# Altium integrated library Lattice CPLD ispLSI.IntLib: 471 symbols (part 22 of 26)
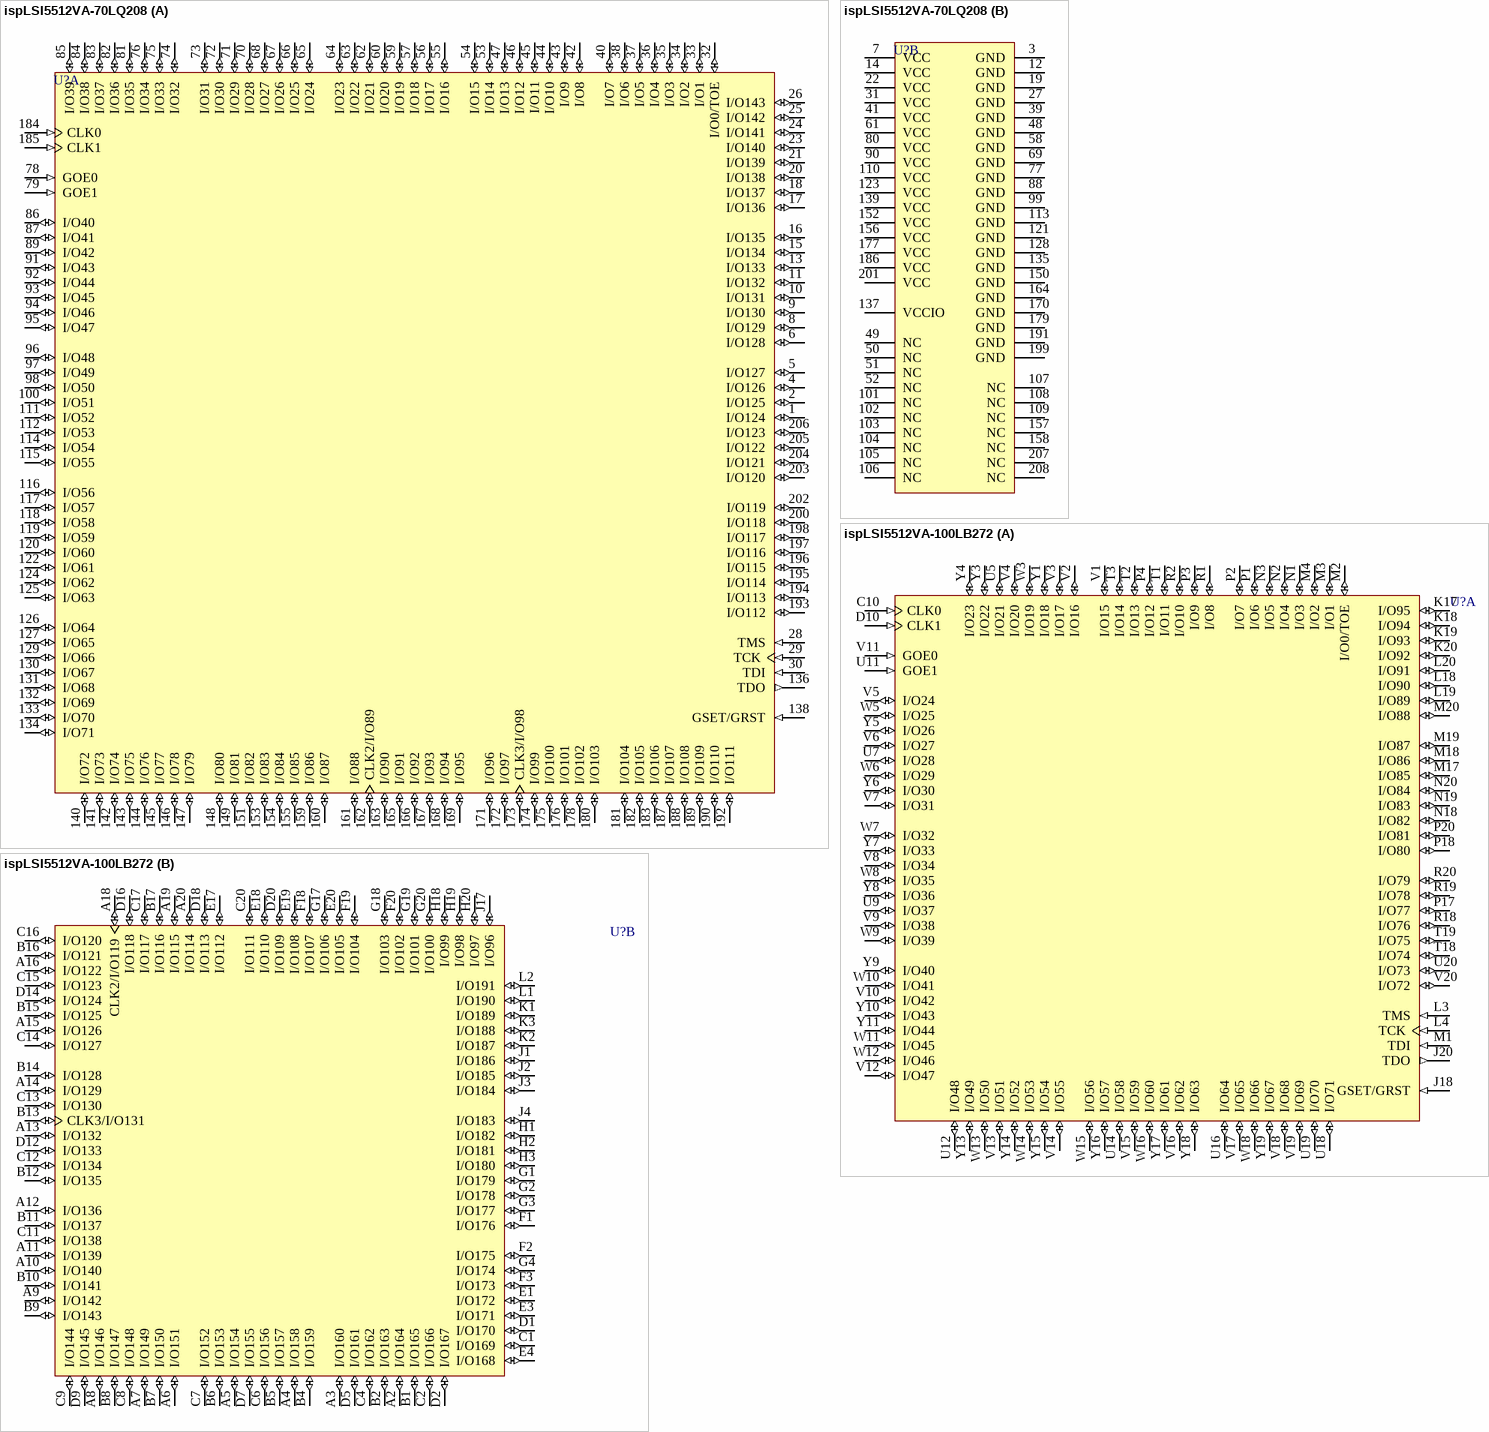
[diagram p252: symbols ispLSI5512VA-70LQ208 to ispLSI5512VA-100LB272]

## ispLSI5512VA-70LQ208
designator U?
In-System Programmable 3.3V SuperWIDE High Density PLD
footprint PQFP208_N (Shrink QFP, 208-Leads, Body 28x28mm, Pitch 0.5mm, IPC Medium Density)
footprint PQFP208_L (Shrink QFP, 208-Leads, Body 28x28mm, Pitch 0.5mm, IPC High Density)
footprint PQFP208_M (Shrink QFP, 208-Leads, Body 28x28mm, Pitch 0.5mm, IPC Low Density)
3D model 5512VA-PQFP208 (208-Pin Plastic Quad Flat Pack (PQFP208))
part A pins: 1 I/O124 (io), 2 I/O125 (io), 4 I/O126 (io), 5 I/O127 (io), 6 I/O128 (io), 8 I/O129 (io), 9 I/O130 (io), 10 I/O131 (io), 11 I/O132 (io), 13 I/O133 (io), 15 I/O134 (io), 16 I/O135 (io), 17 I/O136 (io), 18 I/O137 (io), 20 I/O138 (io), 21 I/O139 (io), 23 I/O140 (io), 24 I/O141 (io), 25 I/O142 (io), 26 I/O143 (io), 28 TMS (in), 29 TCK (in), 30 TDI (in), 32 I/O0/TOE (io), 33 I/O1 (io), 34 I/O2 (io), 35 I/O3 (io), 36 I/O4 (io), 37 I/O5 (io), 38 I/O6 (io), 40 I/O7 (io), 42 I/O8 (io), 43 I/O9 (io), 44 I/O10 (io), 45 I/O11 (io), 46 I/O12 (io), 47 I/O13 (io), 53 I/O14 (io), 54 I/O15 (io), 55 I/O16 (io), 56 I/O17 (io), 57 I/O18 (io), 59 I/O19 (io), 60 I/O20 (io), 62 I/O21 (io), 63 I/O22 (io), 64 I/O23 (io), 65 I/O24 (io), 66 I/O25 (io), 67 I/O26 (io), 68 I/O27 (io), 70 I/O28 (io), 71 I/O29 (io), 72 I/O30 (io), 73 I/O31 (io), 74 I/O32 (io), 75 I/O33 (io), 76 I/O34 (io), 78 GOE0 (in), 79 GOE1 (in), 81 I/O35 (io), 82 I/O36 (io), 83 I/O37 (io), 84 I/O38 (io), 85 I/O39 (io), 86 I/O40 (io), 87 I/O41 (io), 89 I/O42 (io), 91 I/O43 (io), 92 I/O44 (io), 93 I/O45 (io), 94 I/O46 (io), 95 I/O47 (io), 96 I/O48 (io), 97 I/O49 (io), 98 I/O50 (io), 100 I/O51 (io), 111 I/O52 (io), 112 I/O53 (io), 114 I/O54 (io), 115 I/O55 (io), 116 I/O56 (io), 117 I/O57 (io), 118 I/O58 (io), 119 I/O59 (io), 120 I/O60 (io), 122 I/O61 (io), 124 I/O62 (io), 125 I/O63 (io), 126 I/O64 (io), 127 I/O65 (io), 129 I/O66 (io), 130 I/O67 (io), 131 I/O68 (io), 132 I/O69 (io), 133 I/O70 (io), 134 I/O71 (io), 136 TDO (out), 138 GSET/GRST (in), 140 I/O72 (io), 141 I/O73 (io), 142 I/O74 (io), 143 I/O75 (io), 144 I/O76 (io), 145 I/O77 (io), 146 I/O78 (io), 147 I/O79 (io), 148 I/O80 (io), 149 I/O81 (io), 151 I/O82 (io), 153 I/O83 (io), 154 I/O84 (io), 155 I/O85 (io), 159 I/O86 (io), 160 I/O87 (io), 161 I/O88 (io), 162 CLK2/I/O89 (io), 163 I/O90 (io), 165 I/O91 (io), 166 I/O92 (io), 167 I/O93 (io), 168 I/O94 (io), 169 I/O95 (io), 171 I/O96 (io), 172 I/O97 (io), 173 CLK3/I/O98 (io), 174 I/O99 (io), 175 I/O100 (io), 176 I/O101 (io), 178 I/O102 (io), 180 I/O103 (io), 181 I/O104 (io), 182 I/O105 (io), 183 I/O106 (io), 184 CLK0 (in), 185 CLK1 (in), 187 I/O107 (io), 188 I/O108 (io), 189 I/O109 (io), 190 I/O110 (io), 192 I/O111 (io), 193 I/O112 (io), 194 I/O113 (io), 195 I/O114 (io), 196 I/O115 (io), 197 I/O116 (io), 198 I/O117 (io), 200 I/O118 (io), 202 I/O119 (io), 203 I/O120 (io), 204 I/O121 (io), 205 I/O122 (io), 206 I/O123 (io)
part B pins: 3 GND (power), 7 VCC (power), 12 GND (power), 14 VCC (power), 19 GND (power), 22 VCC (power), 27 GND (power), 31 VCC (power), 39 GND (power), 41 VCC (power), 48 GND (power), 49 NC, 50 NC, 51 NC, 52 NC, 58 GND (power), 61 VCC (power), 69 GND (power), 77 GND (power), 80 VCC (power), 88 GND (power), 90 VCC (power), 99 GND (power), 101 NC, 102 NC, 103 NC, 104 NC, 105 NC, 106 NC, 107 NC, 108 NC, 109 NC, 110 VCC (power), 113 GND (power), 121 GND (power), 123 VCC (power), 128 GND (power), 135 GND (power), 137 VCCIO (power), 139 VCC (power), 150 GND (power), 152 VCC (power), 156 VCC (power), 157 NC, 158 NC, 164 GND (power), 170 GND (power), 177 VCC (power), 179 GND (power), 186 VCC (power), 191 GND (power), 199 GND (power), 201 VCC (power), 207 NC, 208 NC

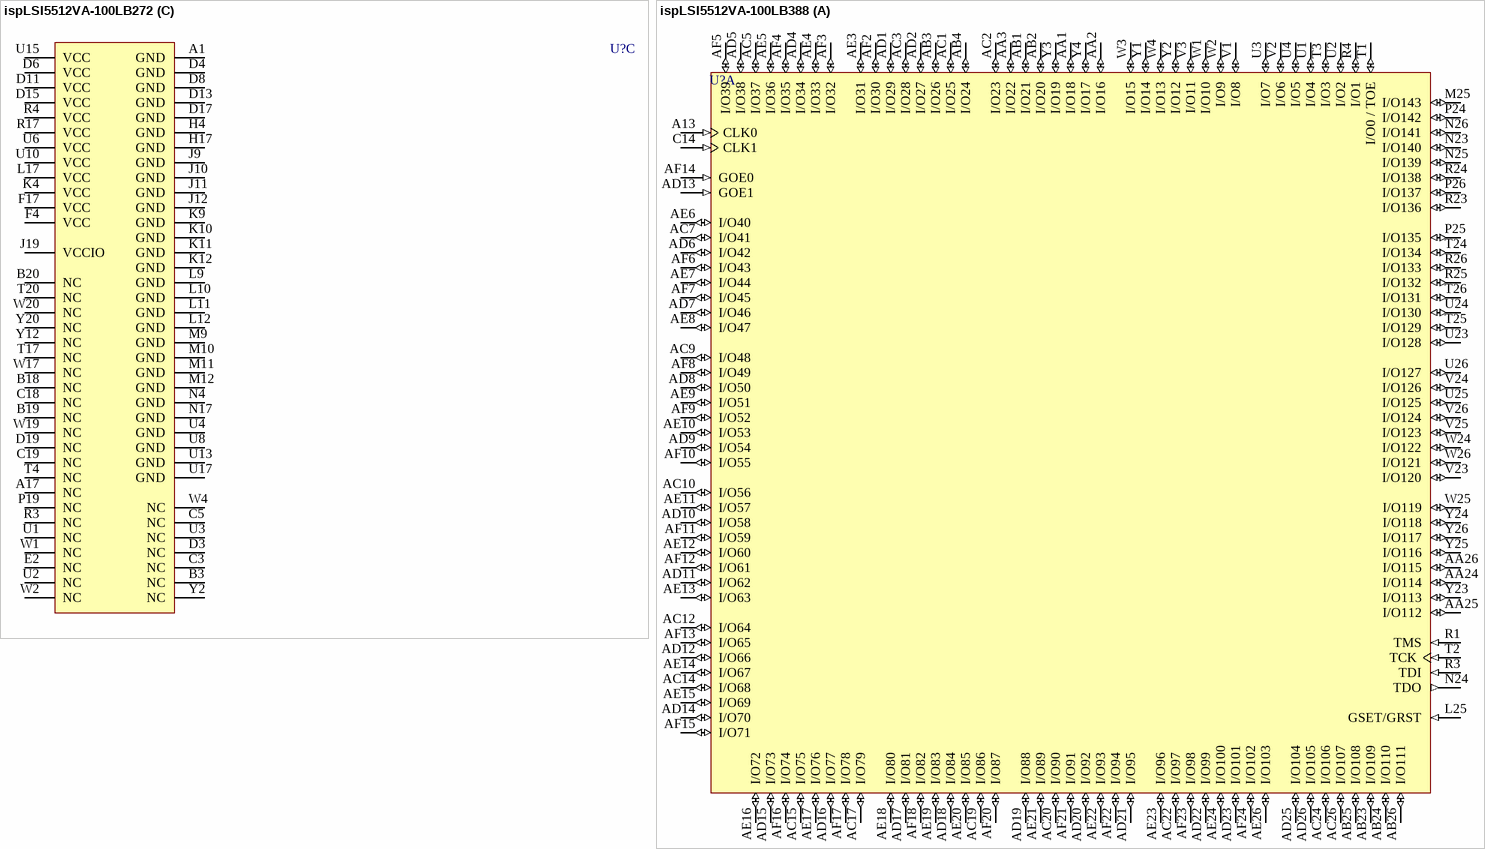
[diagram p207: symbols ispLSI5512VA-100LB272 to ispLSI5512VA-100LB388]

## ispLSI5512VA-100LB272
designator U?
In-System Programmable 3.3V SuperWIDE High Density PLD
footprint BGA272 (BGA, 272-Leads, Body 27x27mm, Pitch 1.27mm)
3D model 5512VA-BGA272 (272-Ball Ball Grid Array (BGA272))
part A pins: C10 CLK0 (in), D10 CLK1 (in), J18 GSET/GRST (in), J20 TDO (out), K17 I/O95 (io), K18 I/O94 (io), K19 I/O93 (io), K20 I/O92 (io), L3 TMS (in), L4 TCK (in), L18 I/O90 (io), L19 I/O89 (io), L20 I/O91 (io), M1 TDI (in), M2 I/O0/TOE (io), M3 I/O1 (io), M4 I/O2 (io), M17 I/O85 (io), M18 I/O86 (io), M19 I/O87 (io), M20 I/O88 (io), N1 I/O3 (io), N2 I/O4 (io), N3 I/O5 (io), N18 I/O82 (io), N19 I/O83 (io), N20 I/O84 (io), P1 I/O6 (io), P2 I/O7 (io), P3 I/O9 (io), P4 I/O12 (io), P17 I/O77 (io), P18 I/O80 (io), P20 I/O81 (io), R1 I/O8 (io), R2 I/O10 (io), R18 I/O76 (io), R19 I/O78 (io), R20 I/O79 (io), T1 I/O11 (io), T2 I/O13 (io), T3 I/O14 (io), T18 I/O74 (io), T19 I/O75 (io), U5 I/O21 (io), U7 I/O28 (io), U9 I/O37 (io), U11 GOE1 (in), U12 I/O48 (io), U14 I/O58 (io), U16 I/O64 (io), U18 I/O71 (io), U19 I/O70 (io), U20 I/O73 (io), V1 I/O15 (io), V2 I/O16 (io), V3 I/O17 (io), V4 I/O20 (io), V5 I/O24 (io), V6 I/O27 (io), V7 I/O31 (io), V8 I/O34 (io), V9 I/O38 (io), V10 I/O42 (io), V11 GOE0 (in), V12 I/O47 (io), V13 I/O51 (io), V14 I/O55 (io), V15 I/O59 (io), V16 I/O62 (io), V17 I/O65 (io), V18 I/O68 (io), V19 I/O69 (io), V20 I/O72 (io), W3 I/O19 (io), W5 I/O25 (io), W6 I/O29 (io), W7 I/O32 (io), W8 I/O35 (io), W9 I/O39 (io), W10 I/O41 (io), W11 I/O45 (io), W12 I/O46 (io), W13 I/O50 (io), W14 I/O53 (io), W15 I/O56 (io), W16 I/O60 (io), W18 I/O66 (io), Y1 I/O18 (io), Y3 I/O22 (io), Y4 I/O23 (io), Y5 I/O26 (io), Y6 I/O30 (io), Y7 I/O33 (io), Y8 I/O36 (io), Y9 I/O40 (io), Y10 I/O43 (io), Y11 I/O44 (io), Y13 I/O49 (io), Y14 I/O52 (io), Y15 I/O54 (io), Y16 I/O57 (io), Y17 I/O61 (io), Y18 I/O63 (io), Y19 I/O67 (io)
part B pins: A2 I/O164 (io), A3 I/O160 (io), A4 I/O158 (io), A5 I/O154 (io), A6 I/O151 (io), A7 I/O149 (io), A8 I/O146 (io), A9 I/O142 (io), A10 I/O140 (io), A11 I/O139 (io), A12 I/O136 (io), A13 I/O132 (io), A14 I/O129 (io), A15 I/O126 (io), A16 I/O122 (io), A18 CLK2/I/O119 (io), A19 I/O115 (io), A20 I/O114 (io), B1 I/O165 (io), B2 I/O163 (io), B4 I/O159 (io), B5 I/O157 (io), B6 I/O153 (io), B7 I/O150 (io), B8 I/O147 (io), B9 I/O143 (io), B10 I/O141 (io), B11 I/O137 (io), B12 I/O135 (io), B13 CLK3/I/O131 (io), B14 I/O128 (io), B15 I/O125 (io), B16 I/O121 (io), B17 I/O116 (io), C1 I/O169 (io), C2 I/O166 (io), C4 I/O162 (io), C6 I/O156 (io), C7 I/O152 (io), C8 I/O148 (io), C9 I/O144 (io), C11 I/O138 (io), C12 I/O134 (io), C13 I/O130 (io), C14 I/O127 (io), C15 I/O123 (io), C16 I/O120 (io), C17 I/O117 (io), C20 I/O111 (io), D1 I/O170 (io), D2 I/O167 (io), D5 I/O161 (io), D7 I/O155 (io), D9 I/O145 (io), D12 I/O133 (io), D14 I/O124 (io), D16 I/O118 (io), D18 I/O113 (io), D20 I/O109 (io), E1 I/O172 (io), E3 I/O171 (io), E4 I/O168 (io), E17 I/O112 (io), E18 I/O110 (io), E19 I/O108 (io), E20 I/O105 (io), F1 I/O176 (io), F2 I/O175 (io), F3 I/O173 (io), F18 I/O107 (io), F19 I/O104 (io), F20 I/O102 (io), G1 I/O179 (io), G2 I/O178 (io), G3 I/O177 (io), G4 I/O174 (io), G17 I/O106 (io), G18 I/O103 (io), G19 I/O101 (io), G20 I/O100 (io), H1 I/O182 (io), H2 I/O181 (io), H3 I/O180 (io), H18 I/O99 (io), H19 I/O98 (io), H20 I/O97 (io), J1 I/O186 (io), J2 I/O185 (io), J3 I/O184 (io), J4 I/O183 (io), J17 I/O96 (io), K1 I/O189 (io), K2 I/O187 (io), K3 I/O188 (io), L1 I/O190 (io), L2 I/O191 (io)
part C pins: A1 GND (power), A17 NC, B3 NC, B18 NC, B19 NC, B20 NC, C3 NC, C5 NC, C18 NC, C19 NC, D3 NC, D4 GND (power), D6 VCC (power), D8 GND (power), D11 VCC (power), D13 GND (power), D15 VCC (power), D17 GND (power), D19 NC, E2 NC, F4 VCC (power), F17 VCC (power), H4 GND (power), H17 GND (power), J9 GND (power), J10 GND (power), J11 GND (power), J12 GND (power), J19 VCCIO (power), K4 VCC (power), K9 GND (power), K10 GND (power), K11 GND (power), K12 GND (power), L9 GND (power), L10 GND (power), L11 GND (power), L12 GND (power), L17 VCC (power), M9 GND (power), M10 GND (power), M11 GND (power), M12 GND (power), N4 GND (power), N17 GND (power), P19 NC, R3 NC, R4 VCC (power), R17 VCC (power), T4 NC, T17 NC, T20 NC, U1 NC, U2 NC, U3 NC, U4 GND (power), U6 VCC (power), U8 GND (power), U10 VCC (power), U13 GND (power), U15 VCC (power), U17 GND (power), W1 NC, W2 NC, W4 NC, W17 NC, W19 NC, W20 NC, Y2 NC, Y12 NC, Y20 NC

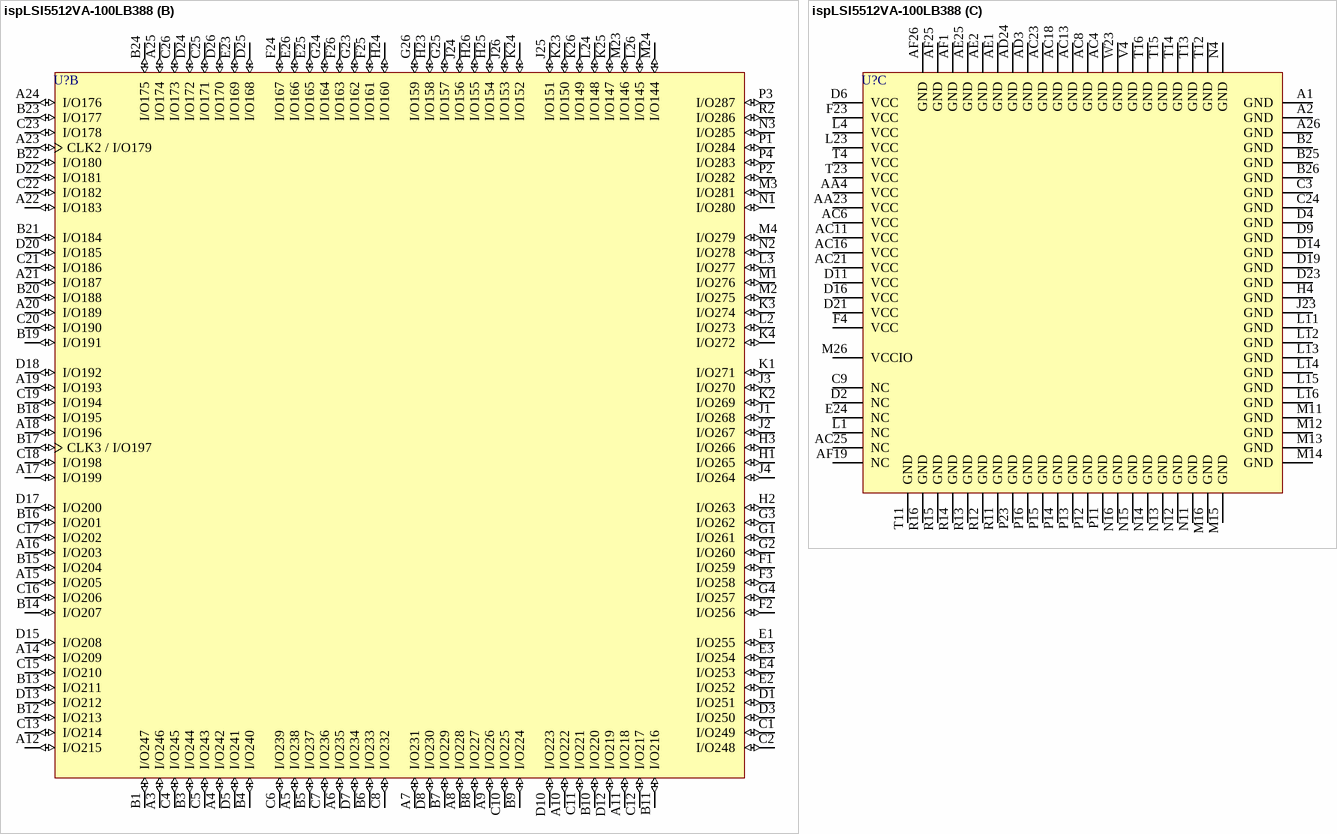
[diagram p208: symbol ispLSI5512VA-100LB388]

## ispLSI5512VA-100LB388
designator U?
In-System Programmable 3.3V SuperWIDE High Density PLD
footprint BGA388 (BGA, 388-Leads, Body 35x35mm, Pitch 1.27mm)
3D model 5512VA-BGA388 (388-Ball Ball Grid Array (BGA388))
part A pins: A13 CLK0 (in), AA1 I/O18 (io), AA2 I/O16 (io), AA3 I/O22 (io), AA24 I/O114 (io), AA25 I/O112 (io), AA26 I/O115 (io), AB1 I/O21 (io), AB2 I/O20 (io), AB3 I/O26 (io), AB4 I/O24 (io), AB23 I/O109 (io), AB24 I/O110 (io), AB25 I/O108 (io), AB26 I/O111 (io), AC1 I/O25 (io), AC2 I/O23 (io), AC3 I/O28 (io), AC5 I/O37 (io), AC7 I/O41 (io), AC9 I/O48 (io), AC10 I/O56 (io), AC12 I/O64 (io), AC14 I/O68 (io), AC15 I/O75 (io), AC17 I/O79 (io), AC19 I/O86 (io), AC20 I/O90 (io), AC22 I/O97 (io), AC24 I/O106 (io), AC26 I/O107 (io), AD1 I/O29 (io), AD2 I/O27 (io), AD4 I/O34 (io), AD5 I/O38 (io), AD6 I/O42 (io), AD7 I/O46 (io), AD8 I/O50 (io), AD9 I/O54 (io), AD10 I/O58 (io), AD11 I/O62 (io), AD12 I/O66 (io), AD13 GOE1 (in), AD14 I/O70 (io), AD15 I/O73 (io), AD16 I/O77 (io), AD17 I/O81 (io), AD18 I/O84 (io), AD19 I/O88 (io), AD20 I/O92 (io), AD21 I/O95 (io), AD22 I/O99 (io), AD23 I/O101 (io), AD25 I/O104 (io), AD26 I/O105 (io), AE3 I/O31 (io), AE4 I/O33 (io), AE5 I/O36 (io), AE6 I/O40 (io), AE7 I/O44 (io), AE8 I/O47 (io), AE9 I/O51 (io), AE10 I/O53 (io), AE11 I/O57 (io), AE12 I/O60 (io), AE13 I/O63 (io), AE14 I/O67 (io), AE15 I/O69 (io), AE16 I/O72 (io), AE17 I/O76 (io), AE18 I/O80 (io), AE19 I/O83 (io), AE20 I/O85 (io), AE21 I/O89 (io), AE22 I/O93 (io), AE23 I/O96 (io), AE24 I/O100 (io), AE26 I/O103 (io), AF2 I/O30 (io), AF3 I/O32 (io), AF4 I/O35 (io), AF5 I/O39 (io), AF6 I/O43 (io), AF7 I/O45 (io), AF8 I/O49 (io), AF9 I/O52 (io), AF10 I/O55 (io), AF11 I/O59 (io), AF12 I/O61 (io), AF13 I/O65 (io), AF14 GOE0 (in), AF15 I/O71 (io), AF16 I/O74 (io), AF17 I/O78 (io), AF18 I/O82 (io), AF20 I/O87 (io), AF21 I/O91 (io), AF22 I/O94 (io), AF23 I/O98 (io), AF24 I/O102 (io), C14 CLK1 (in), L25 GSET/GRST (in), M25 I/O143 (io), N23 I/O140 (io), N24 TDO (out), N25 I/O139 (io), N26 I/O141 (io), P24 I/O142 (io), P25 I/O135 (io), P26 I/O137 (io), R1 TMS (in), R3 TDI (in), R4 I/O1 (io), R23 I/O136 (io), R24 I/O138 (io), R25 I/O132 (io), R26 I/O133 (io), T1 I/O0 / TOE (io), T2 TCK (in), T3 I/O3 (io), T24 I/O134 (io), T25 I/O129 (io), T26 I/O131 (io), U1 I/O4 (io), U2 I/O2 (io), U3 I/O7 (io), U4 I/O5 (io), U23 I/O128 (io), U24 I/O130 (io), U25 I/O125 (io), U26 I/O127 (io), V1 I/O8 (io), V2 I/O6 (io), V3 I/O11 (io), V23 I/O120 (io), V24 I/O126 (io), V25 I/O123 (io), V26 I/O124 (io), W1 I/O10 (io), W2 I/O9 (io), W3 I/O15 (io), W4 I/O13 (io), W24 I/O122 (io), W25 I/O119 (io), W26 I/O121 (io), Y1 I/O14 (io), Y2 I/O12 (io), Y3 I/O19 (io), Y4 I/O17 (io), Y23 I/O113 (io), Y24 I/O118 (io), Y25 I/O116 (io), Y26 I/O117 (io)
part B pins: A3 I/O246 (io), A4 I/O242 (io), A5 I/O238 (io), A6 I/O235 (io), A7 I/O231 (io), A8 I/O228 (io), A9 I/O226 (io), A10 I/O222 (io), A11 I/O218 (io), A12 I/O215 (io), A14 I/O209 (io), A15 I/O205 (io), A16 I/O203 (io), A17 I/O199 (io), A18 I/O196 (io), A19 I/O193 (io), A20 I/O189 (io), A21 I/O187 (io), A22 I/O183 (io), A23 CLK2 / I/O179 (io), A24 I/O176 (io), A25 I/O174 (io), B1 I/O247 (io), B3 I/O244 (io), B4 I/O240 (io), B5 I/O237 (io), B6 I/O233 (io), B7 I/O229 (io), B8 I/O227 (io), B9 I/O224 (io), B10 I/O220 (io), B11 I/O216 (io), B12 I/O213 (io), B13 I/O211 (io), B14 I/O207 (io), B15 I/O204 (io), B16 I/O201 (io), B17 CLK3 / I/O197 (io), B18 I/O195 (io), B19 I/O191 (io), B20 I/O188 (io), B21 I/O184 (io), B22 I/O180 (io), B23 I/O177 (io), B24 I/O175 (io), C1 I/O249 (io), C2 I/O248 (io), C4 I/O245 (io), C5 I/O243 (io), C6 I/O239 (io), C7 I/O236 (io), C8 I/O232 (io), C10 I/O225 (io), C11 I/O221 (io), C12 I/O217 (io), C13 I/O214 (io), C15 I/O210 (io), C16 I/O206 (io), C17 I/O202 (io), C18 I/O198 (io), C19 I/O194 (io), C20 I/O190 (io), C21 I/O186 (io), C22 I/O182 (io), C23 I/O178 (io), C25 I/O171 (io), C26 I/O173 (io), D1 I/O251 (io), D3 I/O250 (io), D5 I/O241 (io), D7 I/O234 (io), D8 I/O230 (io), D10 I/O223 (io), D12 I/O219 (io), D13 I/O212 (io), D15 I/O208 (io), D17 I/O200 (io), D18 I/O192 (io), D20 I/O185 (io), D22 I/O181 (io), D24 I/O172 (io), D25 I/O168 (io), D26 I/O170 (io), E1 I/O255 (io), E2 I/O252 (io), E3 I/O254 (io), E4 I/O253 (io), E23 I/O169 (io), E25 I/O165 (io), E26 I/O166 (io), F1 I/O259 (io), F2 I/O256 (io), F3 I/O258 (io), F24 I/O167 (io), F25 I/O161 (io), F26 I/O163 (io), G1 I/O261 (io), G2 I/O260 (io), G3 I/O262 (io), G4 I/O257 (io), G23 I/O162 (io), G24 I/O164 (io), G25 I/O157 (io), G26 I/O159 (io), H1 I/O265 (io), H2 I/O263 (io), H3 I/O266 (io), H23 I/O158 (io), H24 I/O160 (io), H25 I/O154 (io), H26 I/O155 (io), J1 I/O268 (io), J2 I/O267 (io), J3 I/O270 (io), J4 I/O264 (io), J24 I/O156 (io), J25 I/O151 (io), J26 I/O153 (io), K1 I/O271 (io), K2 I/O269 (io), K3 I/O274 (io), K4 I/O272 (io), K23 I/O150 (io), K24 I/O152 (io), K25 I/O147 (io), K26 I/O149 (io), L2 I/O273 (io), L3 I/O277 (io), L24 I/O148 (io), L26 I/O145 (io), M1 I/O276 (io), M2 I/O275 (io), M3 I/O281 (io), M4 I/O279 (io), M23 I/O146 (io), M24 I/O144 (io), N1 I/O280 (io), N2 I/O278 (io), N3 I/O285 (io), P1 I/O284 (io), P2 I/O282 (io), P3 I/O287 (io), P4 I/O283 (io), R2 I/O286 (io)
part C pins: A1 GND (power), A2 GND (power), A26 GND (power), AA4 VCC (power), AA23 VCC (power), AC4 GND (power), AC6 VCC (power), AC8 GND (power), AC11 VCC (power), AC13 GND (power), AC16 VCC (power), AC18 GND (power), AC21 VCC (power), AC23 GND (power), AC25 NC, AD3 GND (power), AD24 GND (power), AE1 GND (power), AE2 GND (power), AE25 GND (power), AF1 GND (power), AF19 NC, AF25 GND (power), AF26 GND (power), B2 GND (power), B25 GND (power), B26 GND (power), C3 GND (power), C9 NC, C24 GND (power), D2 NC, D4 GND (power), D6 VCC (power), D9 GND (power), D11 VCC (power), D14 GND (power), D16 VCC (power), D19 GND (power), D21 VCC (power), D23 GND (power), E24 NC, F4 VCC (power), F23 VCC (power), H4 GND (power), J23 GND (power), L1 NC, L4 VCC (power), L11 GND (power), L12 GND (power), L13 GND (power), L14 GND (power), L15 GND (power), L16 GND (power), L23 VCC (power), M11 GND (power), M12 GND (power), M13 GND (power), M14 GND (power), M15 GND (power), M16 GND (power), M26 VCCIO (power), N4 GND (power), N11 GND (power), N12 GND (power), N13 GND (power), N14 GND (power), N15 GND (power), N16 GND (power), P11 GND (power), P12 GND (power), P13 GND (power), P14 GND (power), P15 GND (power), P16 GND (power), P23 GND (power), R11 GND (power), R12 GND (power), R13 GND (power), R14 GND (power), R15 GND (power), R16 GND (power), T4 VCC (power), T11 GND (power), T12 GND (power), T13 GND (power), T14 GND (power), T15 GND (power), T16 GND (power), T23 VCC (power), V4 GND (power), W23 GND (power)

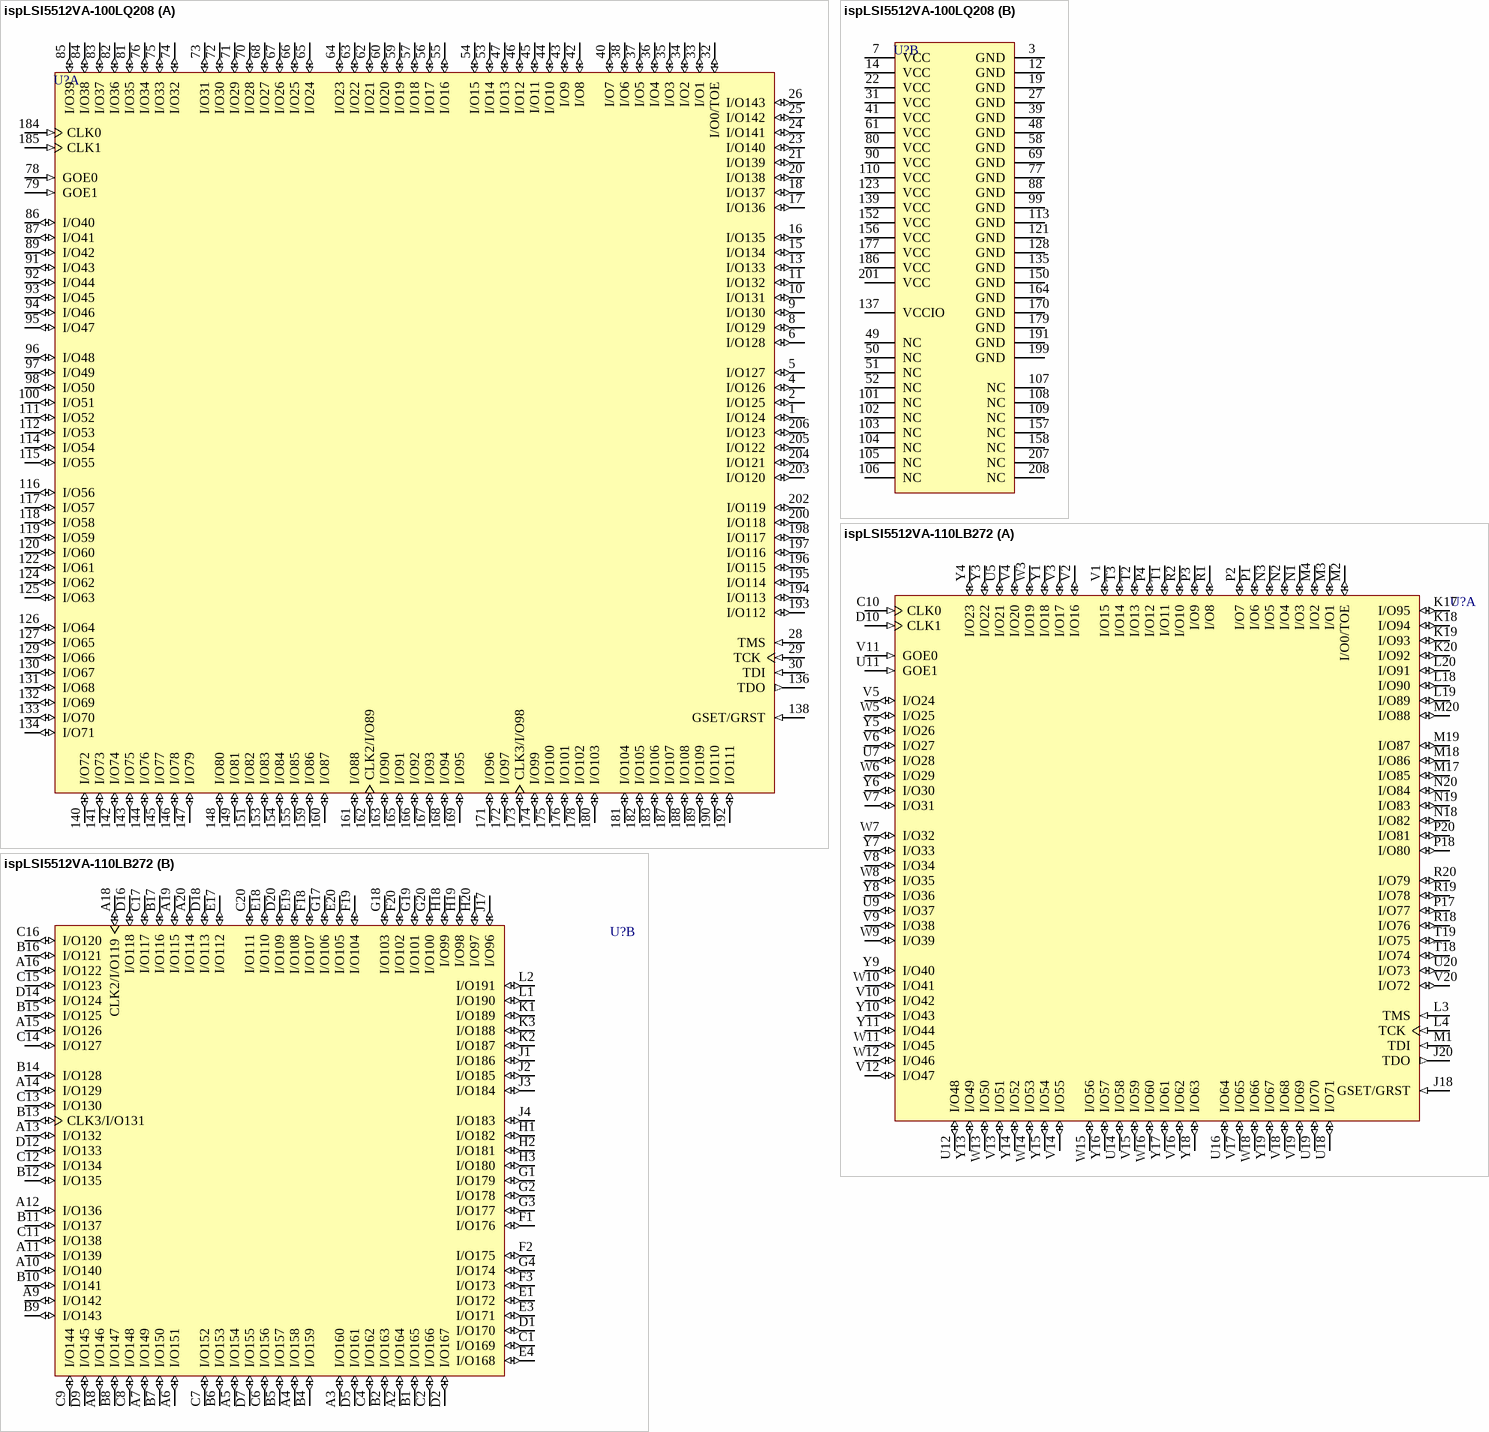
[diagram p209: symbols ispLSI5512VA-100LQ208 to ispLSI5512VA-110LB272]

## ispLSI5512VA-100LQ208
designator U?
In-System Programmable 3.3V SuperWIDE High Density PLD
footprint PQFP208_N (Shrink QFP, 208-Leads, Body 28x28mm, Pitch 0.5mm, IPC Medium Density)
footprint PQFP208_L (Shrink QFP, 208-Leads, Body 28x28mm, Pitch 0.5mm, IPC High Density)
footprint PQFP208_M (Shrink QFP, 208-Leads, Body 28x28mm, Pitch 0.5mm, IPC Low Density)
3D model 5512VA-PQFP208 (208-Pin Plastic Quad Flat Pack (PQFP208))
part A pins: 1 I/O124 (io), 2 I/O125 (io), 4 I/O126 (io), 5 I/O127 (io), 6 I/O128 (io), 8 I/O129 (io), 9 I/O130 (io), 10 I/O131 (io), 11 I/O132 (io), 13 I/O133 (io), 15 I/O134 (io), 16 I/O135 (io), 17 I/O136 (io), 18 I/O137 (io), 20 I/O138 (io), 21 I/O139 (io), 23 I/O140 (io), 24 I/O141 (io), 25 I/O142 (io), 26 I/O143 (io), 28 TMS (in), 29 TCK (in), 30 TDI (in), 32 I/O0/TOE (io), 33 I/O1 (io), 34 I/O2 (io), 35 I/O3 (io), 36 I/O4 (io), 37 I/O5 (io), 38 I/O6 (io), 40 I/O7 (io), 42 I/O8 (io), 43 I/O9 (io), 44 I/O10 (io), 45 I/O11 (io), 46 I/O12 (io), 47 I/O13 (io), 53 I/O14 (io), 54 I/O15 (io), 55 I/O16 (io), 56 I/O17 (io), 57 I/O18 (io), 59 I/O19 (io), 60 I/O20 (io), 62 I/O21 (io), 63 I/O22 (io), 64 I/O23 (io), 65 I/O24 (io), 66 I/O25 (io), 67 I/O26 (io), 68 I/O27 (io), 70 I/O28 (io), 71 I/O29 (io), 72 I/O30 (io), 73 I/O31 (io), 74 I/O32 (io), 75 I/O33 (io), 76 I/O34 (io), 78 GOE0 (in), 79 GOE1 (in), 81 I/O35 (io), 82 I/O36 (io), 83 I/O37 (io), 84 I/O38 (io), 85 I/O39 (io), 86 I/O40 (io), 87 I/O41 (io), 89 I/O42 (io), 91 I/O43 (io), 92 I/O44 (io), 93 I/O45 (io), 94 I/O46 (io), 95 I/O47 (io), 96 I/O48 (io), 97 I/O49 (io), 98 I/O50 (io), 100 I/O51 (io), 111 I/O52 (io), 112 I/O53 (io), 114 I/O54 (io), 115 I/O55 (io), 116 I/O56 (io), 117 I/O57 (io), 118 I/O58 (io), 119 I/O59 (io), 120 I/O60 (io), 122 I/O61 (io), 124 I/O62 (io), 125 I/O63 (io), 126 I/O64 (io), 127 I/O65 (io), 129 I/O66 (io), 130 I/O67 (io), 131 I/O68 (io), 132 I/O69 (io), 133 I/O70 (io), 134 I/O71 (io), 136 TDO (out), 138 GSET/GRST (in), 140 I/O72 (io), 141 I/O73 (io), 142 I/O74 (io), 143 I/O75 (io), 144 I/O76 (io), 145 I/O77 (io), 146 I/O78 (io), 147 I/O79 (io), 148 I/O80 (io), 149 I/O81 (io), 151 I/O82 (io), 153 I/O83 (io), 154 I/O84 (io), 155 I/O85 (io), 159 I/O86 (io), 160 I/O87 (io), 161 I/O88 (io), 162 CLK2/I/O89 (io), 163 I/O90 (io), 165 I/O91 (io), 166 I/O92 (io), 167 I/O93 (io), 168 I/O94 (io), 169 I/O95 (io), 171 I/O96 (io), 172 I/O97 (io), 173 CLK3/I/O98 (io), 174 I/O99 (io), 175 I/O100 (io), 176 I/O101 (io), 178 I/O102 (io), 180 I/O103 (io), 181 I/O104 (io), 182 I/O105 (io), 183 I/O106 (io), 184 CLK0 (in), 185 CLK1 (in), 187 I/O107 (io), 188 I/O108 (io), 189 I/O109 (io), 190 I/O110 (io), 192 I/O111 (io), 193 I/O112 (io), 194 I/O113 (io), 195 I/O114 (io), 196 I/O115 (io), 197 I/O116 (io), 198 I/O117 (io), 200 I/O118 (io), 202 I/O119 (io), 203 I/O120 (io), 204 I/O121 (io), 205 I/O122 (io), 206 I/O123 (io)
part B pins: 3 GND (power), 7 VCC (power), 12 GND (power), 14 VCC (power), 19 GND (power), 22 VCC (power), 27 GND (power), 31 VCC (power), 39 GND (power), 41 VCC (power), 48 GND (power), 49 NC, 50 NC, 51 NC, 52 NC, 58 GND (power), 61 VCC (power), 69 GND (power), 77 GND (power), 80 VCC (power), 88 GND (power), 90 VCC (power), 99 GND (power), 101 NC, 102 NC, 103 NC, 104 NC, 105 NC, 106 NC, 107 NC, 108 NC, 109 NC, 110 VCC (power), 113 GND (power), 121 GND (power), 123 VCC (power), 128 GND (power), 135 GND (power), 137 VCCIO (power), 139 VCC (power), 150 GND (power), 152 VCC (power), 156 VCC (power), 157 NC, 158 NC, 164 GND (power), 170 GND (power), 177 VCC (power), 179 GND (power), 186 VCC (power), 191 GND (power), 199 GND (power), 201 VCC (power), 207 NC, 208 NC

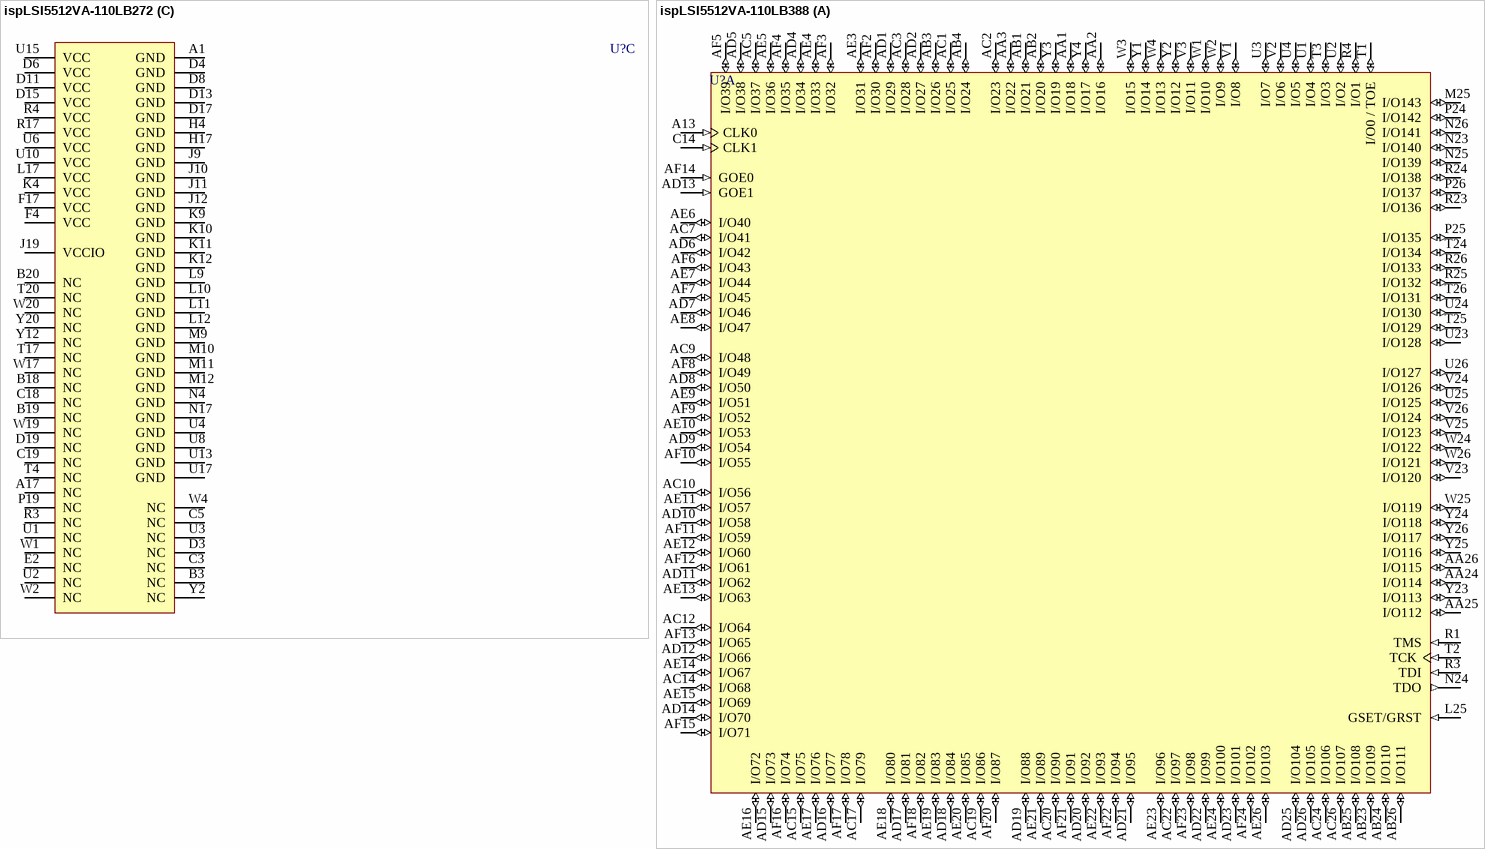
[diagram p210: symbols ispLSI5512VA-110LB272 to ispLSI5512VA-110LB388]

## ispLSI5512VA-110LB272
designator U?
In-System Programmable 3.3V SuperWIDE High Density PLD
footprint BGA272 (BGA, 272-Leads, Body 27x27mm, Pitch 1.27mm)
3D model 5512VA-BGA272 (272-Ball Ball Grid Array (BGA272))
part A pins: C10 CLK0 (in), D10 CLK1 (in), J18 GSET/GRST (in), J20 TDO (out), K17 I/O95 (io), K18 I/O94 (io), K19 I/O93 (io), K20 I/O92 (io), L3 TMS (in), L4 TCK (in), L18 I/O90 (io), L19 I/O89 (io), L20 I/O91 (io), M1 TDI (in), M2 I/O0/TOE (io), M3 I/O1 (io), M4 I/O2 (io), M17 I/O85 (io), M18 I/O86 (io), M19 I/O87 (io), M20 I/O88 (io), N1 I/O3 (io), N2 I/O4 (io), N3 I/O5 (io), N18 I/O82 (io), N19 I/O83 (io), N20 I/O84 (io), P1 I/O6 (io), P2 I/O7 (io), P3 I/O9 (io), P4 I/O12 (io), P17 I/O77 (io), P18 I/O80 (io), P20 I/O81 (io), R1 I/O8 (io), R2 I/O10 (io), R18 I/O76 (io), R19 I/O78 (io), R20 I/O79 (io), T1 I/O11 (io), T2 I/O13 (io), T3 I/O14 (io), T18 I/O74 (io), T19 I/O75 (io), U5 I/O21 (io), U7 I/O28 (io), U9 I/O37 (io), U11 GOE1 (in), U12 I/O48 (io), U14 I/O58 (io), U16 I/O64 (io), U18 I/O71 (io), U19 I/O70 (io), U20 I/O73 (io), V1 I/O15 (io), V2 I/O16 (io), V3 I/O17 (io), V4 I/O20 (io), V5 I/O24 (io), V6 I/O27 (io), V7 I/O31 (io), V8 I/O34 (io), V9 I/O38 (io), V10 I/O42 (io), V11 GOE0 (in), V12 I/O47 (io), V13 I/O51 (io), V14 I/O55 (io), V15 I/O59 (io), V16 I/O62 (io), V17 I/O65 (io), V18 I/O68 (io), V19 I/O69 (io), V20 I/O72 (io), W3 I/O19 (io), W5 I/O25 (io), W6 I/O29 (io), W7 I/O32 (io), W8 I/O35 (io), W9 I/O39 (io), W10 I/O41 (io), W11 I/O45 (io), W12 I/O46 (io), W13 I/O50 (io), W14 I/O53 (io), W15 I/O56 (io), W16 I/O60 (io), W18 I/O66 (io), Y1 I/O18 (io), Y3 I/O22 (io), Y4 I/O23 (io), Y5 I/O26 (io), Y6 I/O30 (io), Y7 I/O33 (io), Y8 I/O36 (io), Y9 I/O40 (io), Y10 I/O43 (io), Y11 I/O44 (io), Y13 I/O49 (io), Y14 I/O52 (io), Y15 I/O54 (io), Y16 I/O57 (io), Y17 I/O61 (io), Y18 I/O63 (io), Y19 I/O67 (io)
part B pins: A2 I/O164 (io), A3 I/O160 (io), A4 I/O158 (io), A5 I/O154 (io), A6 I/O151 (io), A7 I/O149 (io), A8 I/O146 (io), A9 I/O142 (io), A10 I/O140 (io), A11 I/O139 (io), A12 I/O136 (io), A13 I/O132 (io), A14 I/O129 (io), A15 I/O126 (io), A16 I/O122 (io), A18 CLK2/I/O119 (io), A19 I/O115 (io), A20 I/O114 (io), B1 I/O165 (io), B2 I/O163 (io), B4 I/O159 (io), B5 I/O157 (io), B6 I/O153 (io), B7 I/O150 (io), B8 I/O147 (io), B9 I/O143 (io), B10 I/O141 (io), B11 I/O137 (io), B12 I/O135 (io), B13 CLK3/I/O131 (io), B14 I/O128 (io), B15 I/O125 (io), B16 I/O121 (io), B17 I/O116 (io), C1 I/O169 (io), C2 I/O166 (io), C4 I/O162 (io), C6 I/O156 (io), C7 I/O152 (io), C8 I/O148 (io), C9 I/O144 (io), C11 I/O138 (io), C12 I/O134 (io), C13 I/O130 (io), C14 I/O127 (io), C15 I/O123 (io), C16 I/O120 (io), C17 I/O117 (io), C20 I/O111 (io), D1 I/O170 (io), D2 I/O167 (io), D5 I/O161 (io), D7 I/O155 (io), D9 I/O145 (io), D12 I/O133 (io), D14 I/O124 (io), D16 I/O118 (io), D18 I/O113 (io), D20 I/O109 (io), E1 I/O172 (io), E3 I/O171 (io), E4 I/O168 (io), E17 I/O112 (io), E18 I/O110 (io), E19 I/O108 (io), E20 I/O105 (io), F1 I/O176 (io), F2 I/O175 (io), F3 I/O173 (io), F18 I/O107 (io), F19 I/O104 (io), F20 I/O102 (io), G1 I/O179 (io), G2 I/O178 (io), G3 I/O177 (io), G4 I/O174 (io), G17 I/O106 (io), G18 I/O103 (io), G19 I/O101 (io), G20 I/O100 (io), H1 I/O182 (io), H2 I/O181 (io), H3 I/O180 (io), H18 I/O99 (io), H19 I/O98 (io), H20 I/O97 (io), J1 I/O186 (io), J2 I/O185 (io), J3 I/O184 (io), J4 I/O183 (io), J17 I/O96 (io), K1 I/O189 (io), K2 I/O187 (io), K3 I/O188 (io), L1 I/O190 (io), L2 I/O191 (io)
part C pins: A1 GND (power), A17 NC, B3 NC, B18 NC, B19 NC, B20 NC, C3 NC, C5 NC, C18 NC, C19 NC, D3 NC, D4 GND (power), D6 VCC (power), D8 GND (power), D11 VCC (power), D13 GND (power), D15 VCC (power), D17 GND (power), D19 NC, E2 NC, F4 VCC (power), F17 VCC (power), H4 GND (power), H17 GND (power), J9 GND (power), J10 GND (power), J11 GND (power), J12 GND (power), J19 VCCIO (power), K4 VCC (power), K9 GND (power), K10 GND (power), K11 GND (power), K12 GND (power), L9 GND (power), L10 GND (power), L11 GND (power), L12 GND (power), L17 VCC (power), M9 GND (power), M10 GND (power), M11 GND (power), M12 GND (power), N4 GND (power), N17 GND (power), P19 NC, R3 NC, R4 VCC (power), R17 VCC (power), T4 NC, T17 NC, T20 NC, U1 NC, U2 NC, U3 NC, U4 GND (power), U6 VCC (power), U8 GND (power), U10 VCC (power), U13 GND (power), U15 VCC (power), U17 GND (power), W1 NC, W2 NC, W4 NC, W17 NC, W19 NC, W20 NC, Y2 NC, Y12 NC, Y20 NC

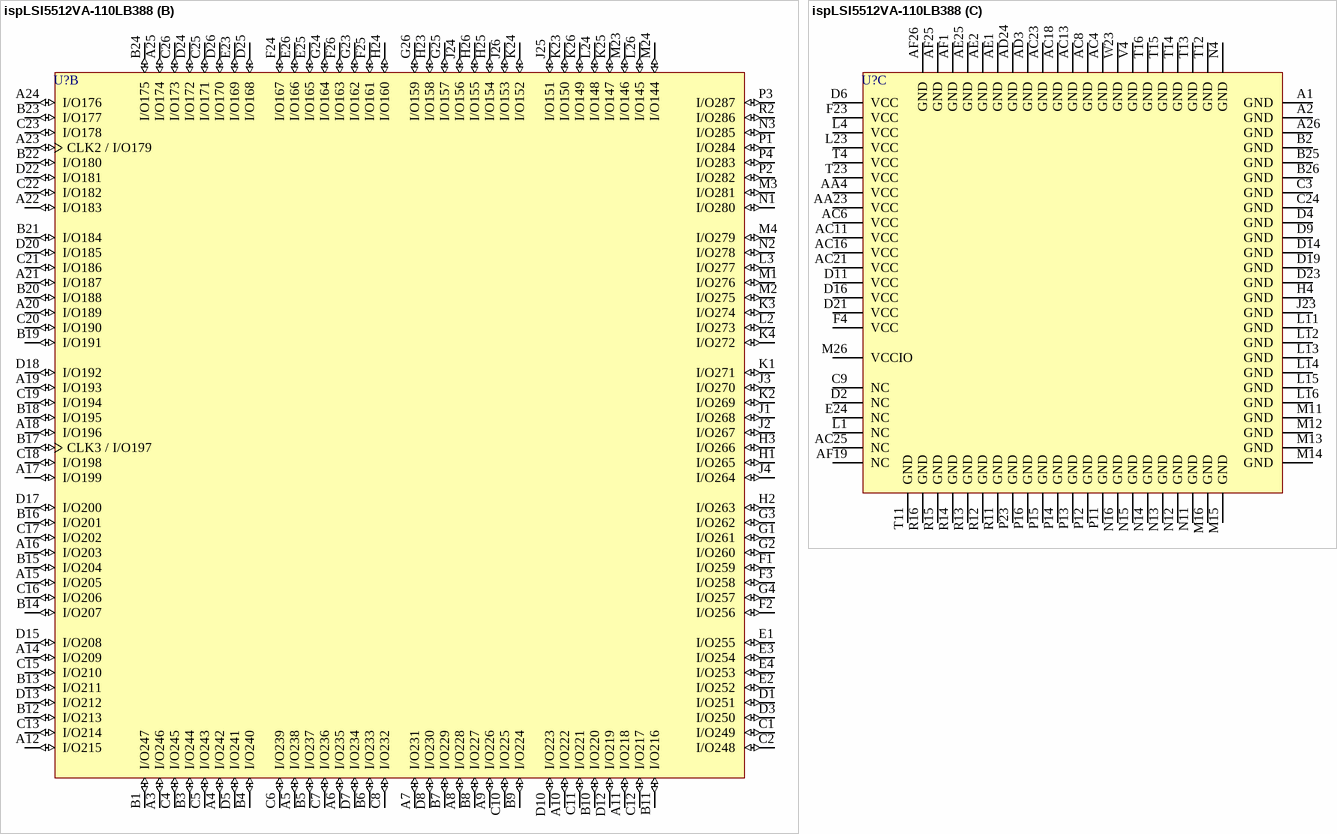
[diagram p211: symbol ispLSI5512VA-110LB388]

## ispLSI5512VA-110LB388
designator U?
In-System Programmable 3.3V SuperWIDE High Density PLD
footprint BGA388 (BGA, 388-Leads, Body 35x35mm, Pitch 1.27mm)
3D model 5512VA-BGA388 (388-Ball Ball Grid Array (BGA388))
part A pins: A13 CLK0 (in), AA1 I/O18 (io), AA2 I/O16 (io), AA3 I/O22 (io), AA24 I/O114 (io), AA25 I/O112 (io), AA26 I/O115 (io), AB1 I/O21 (io), AB2 I/O20 (io), AB3 I/O26 (io), AB4 I/O24 (io), AB23 I/O109 (io), AB24 I/O110 (io), AB25 I/O108 (io), AB26 I/O111 (io), AC1 I/O25 (io), AC2 I/O23 (io), AC3 I/O28 (io), AC5 I/O37 (io), AC7 I/O41 (io), AC9 I/O48 (io), AC10 I/O56 (io), AC12 I/O64 (io), AC14 I/O68 (io), AC15 I/O75 (io), AC17 I/O79 (io), AC19 I/O86 (io), AC20 I/O90 (io), AC22 I/O97 (io), AC24 I/O106 (io), AC26 I/O107 (io), AD1 I/O29 (io), AD2 I/O27 (io), AD4 I/O34 (io), AD5 I/O38 (io), AD6 I/O42 (io), AD7 I/O46 (io), AD8 I/O50 (io), AD9 I/O54 (io), AD10 I/O58 (io), AD11 I/O62 (io), AD12 I/O66 (io), AD13 GOE1 (in), AD14 I/O70 (io), AD15 I/O73 (io), AD16 I/O77 (io), AD17 I/O81 (io), AD18 I/O84 (io), AD19 I/O88 (io), AD20 I/O92 (io), AD21 I/O95 (io), AD22 I/O99 (io), AD23 I/O101 (io), AD25 I/O104 (io), AD26 I/O105 (io), AE3 I/O31 (io), AE4 I/O33 (io), AE5 I/O36 (io), AE6 I/O40 (io), AE7 I/O44 (io), AE8 I/O47 (io), AE9 I/O51 (io), AE10 I/O53 (io), AE11 I/O57 (io), AE12 I/O60 (io), AE13 I/O63 (io), AE14 I/O67 (io), AE15 I/O69 (io), AE16 I/O72 (io), AE17 I/O76 (io), AE18 I/O80 (io), AE19 I/O83 (io), AE20 I/O85 (io), AE21 I/O89 (io), AE22 I/O93 (io), AE23 I/O96 (io), AE24 I/O100 (io), AE26 I/O103 (io), AF2 I/O30 (io), AF3 I/O32 (io), AF4 I/O35 (io), AF5 I/O39 (io), AF6 I/O43 (io), AF7 I/O45 (io), AF8 I/O49 (io), AF9 I/O52 (io), AF10 I/O55 (io), AF11 I/O59 (io), AF12 I/O61 (io), AF13 I/O65 (io), AF14 GOE0 (in), AF15 I/O71 (io), AF16 I/O74 (io), AF17 I/O78 (io), AF18 I/O82 (io), AF20 I/O87 (io), AF21 I/O91 (io), AF22 I/O94 (io), AF23 I/O98 (io), AF24 I/O102 (io), C14 CLK1 (in), L25 GSET/GRST (in), M25 I/O143 (io), N23 I/O140 (io), N24 TDO (out), N25 I/O139 (io), N26 I/O141 (io), P24 I/O142 (io), P25 I/O135 (io), P26 I/O137 (io), R1 TMS (in), R3 TDI (in), R4 I/O1 (io), R23 I/O136 (io), R24 I/O138 (io), R25 I/O132 (io), R26 I/O133 (io), T1 I/O0 / TOE (io), T2 TCK (in), T3 I/O3 (io), T24 I/O134 (io), T25 I/O129 (io), T26 I/O131 (io), U1 I/O4 (io), U2 I/O2 (io), U3 I/O7 (io), U4 I/O5 (io), U23 I/O128 (io), U24 I/O130 (io), U25 I/O125 (io), U26 I/O127 (io), V1 I/O8 (io), V2 I/O6 (io), V3 I/O11 (io), V23 I/O120 (io), V24 I/O126 (io), V25 I/O123 (io), V26 I/O124 (io), W1 I/O10 (io), W2 I/O9 (io), W3 I/O15 (io), W4 I/O13 (io), W24 I/O122 (io), W25 I/O119 (io), W26 I/O121 (io), Y1 I/O14 (io), Y2 I/O12 (io), Y3 I/O19 (io), Y4 I/O17 (io), Y23 I/O113 (io), Y24 I/O118 (io), Y25 I/O116 (io), Y26 I/O117 (io)
part B pins: A3 I/O246 (io), A4 I/O242 (io), A5 I/O238 (io), A6 I/O235 (io), A7 I/O231 (io), A8 I/O228 (io), A9 I/O226 (io), A10 I/O222 (io), A11 I/O218 (io), A12 I/O215 (io), A14 I/O209 (io), A15 I/O205 (io), A16 I/O203 (io), A17 I/O199 (io), A18 I/O196 (io), A19 I/O193 (io), A20 I/O189 (io), A21 I/O187 (io), A22 I/O183 (io), A23 CLK2 / I/O179 (io), A24 I/O176 (io), A25 I/O174 (io), B1 I/O247 (io), B3 I/O244 (io), B4 I/O240 (io), B5 I/O237 (io), B6 I/O233 (io), B7 I/O229 (io), B8 I/O227 (io), B9 I/O224 (io), B10 I/O220 (io), B11 I/O216 (io), B12 I/O213 (io), B13 I/O211 (io), B14 I/O207 (io), B15 I/O204 (io), B16 I/O201 (io), B17 CLK3 / I/O197 (io), B18 I/O195 (io), B19 I/O191 (io), B20 I/O188 (io), B21 I/O184 (io), B22 I/O180 (io), B23 I/O177 (io), B24 I/O175 (io), C1 I/O249 (io), C2 I/O248 (io), C4 I/O245 (io), C5 I/O243 (io), C6 I/O239 (io), C7 I/O236 (io), C8 I/O232 (io), C10 I/O225 (io), C11 I/O221 (io), C12 I/O217 (io), C13 I/O214 (io), C15 I/O210 (io), C16 I/O206 (io), C17 I/O202 (io), C18 I/O198 (io), C19 I/O194 (io), C20 I/O190 (io), C21 I/O186 (io), C22 I/O182 (io), C23 I/O178 (io), C25 I/O171 (io), C26 I/O173 (io), D1 I/O251 (io), D3 I/O250 (io), D5 I/O241 (io), D7 I/O234 (io), D8 I/O230 (io), D10 I/O223 (io), D12 I/O219 (io), D13 I/O212 (io), D15 I/O208 (io), D17 I/O200 (io), D18 I/O192 (io), D20 I/O185 (io), D22 I/O181 (io), D24 I/O172 (io), D25 I/O168 (io), D26 I/O170 (io), E1 I/O255 (io), E2 I/O252 (io), E3 I/O254 (io), E4 I/O253 (io), E23 I/O169 (io), E25 I/O165 (io), E26 I/O166 (io), F1 I/O259 (io), F2 I/O256 (io), F3 I/O258 (io), F24 I/O167 (io), F25 I/O161 (io), F26 I/O163 (io), G1 I/O261 (io), G2 I/O260 (io), G3 I/O262 (io), G4 I/O257 (io), G23 I/O162 (io), G24 I/O164 (io), G25 I/O157 (io), G26 I/O159 (io), H1 I/O265 (io), H2 I/O263 (io), H3 I/O266 (io), H23 I/O158 (io), H24 I/O160 (io), H25 I/O154 (io), H26 I/O155 (io), J1 I/O268 (io), J2 I/O267 (io), J3 I/O270 (io), J4 I/O264 (io), J24 I/O156 (io), J25 I/O151 (io), J26 I/O153 (io), K1 I/O271 (io), K2 I/O269 (io), K3 I/O274 (io), K4 I/O272 (io), K23 I/O150 (io), K24 I/O152 (io), K25 I/O147 (io), K26 I/O149 (io), L2 I/O273 (io), L3 I/O277 (io), L24 I/O148 (io), L26 I/O145 (io), M1 I/O276 (io), M2 I/O275 (io), M3 I/O281 (io), M4 I/O279 (io), M23 I/O146 (io), M24 I/O144 (io), N1 I/O280 (io), N2 I/O278 (io), N3 I/O285 (io), P1 I/O284 (io), P2 I/O282 (io), P3 I/O287 (io), P4 I/O283 (io), R2 I/O286 (io)
part C pins: A1 GND (power), A2 GND (power), A26 GND (power), AA4 VCC (power), AA23 VCC (power), AC4 GND (power), AC6 VCC (power), AC8 GND (power), AC11 VCC (power), AC13 GND (power), AC16 VCC (power), AC18 GND (power), AC21 VCC (power), AC23 GND (power), AC25 NC, AD3 GND (power), AD24 GND (power), AE1 GND (power), AE2 GND (power), AE25 GND (power), AF1 GND (power), AF19 NC, AF25 GND (power), AF26 GND (power), B2 GND (power), B25 GND (power), B26 GND (power), C3 GND (power), C9 NC, C24 GND (power), D2 NC, D4 GND (power), D6 VCC (power), D9 GND (power), D11 VCC (power), D14 GND (power), D16 VCC (power), D19 GND (power), D21 VCC (power), D23 GND (power), E24 NC, F4 VCC (power), F23 VCC (power), H4 GND (power), J23 GND (power), L1 NC, L4 VCC (power), L11 GND (power), L12 GND (power), L13 GND (power), L14 GND (power), L15 GND (power), L16 GND (power), L23 VCC (power), M11 GND (power), M12 GND (power), M13 GND (power), M14 GND (power), M15 GND (power), M16 GND (power), M26 VCCIO (power), N4 GND (power), N11 GND (power), N12 GND (power), N13 GND (power), N14 GND (power), N15 GND (power), N16 GND (power), P11 GND (power), P12 GND (power), P13 GND (power), P14 GND (power), P15 GND (power), P16 GND (power), P23 GND (power), R11 GND (power), R12 GND (power), R13 GND (power), R14 GND (power), R15 GND (power), R16 GND (power), T4 VCC (power), T11 GND (power), T12 GND (power), T13 GND (power), T14 GND (power), T15 GND (power), T16 GND (power), T23 VCC (power), V4 GND (power), W23 GND (power)

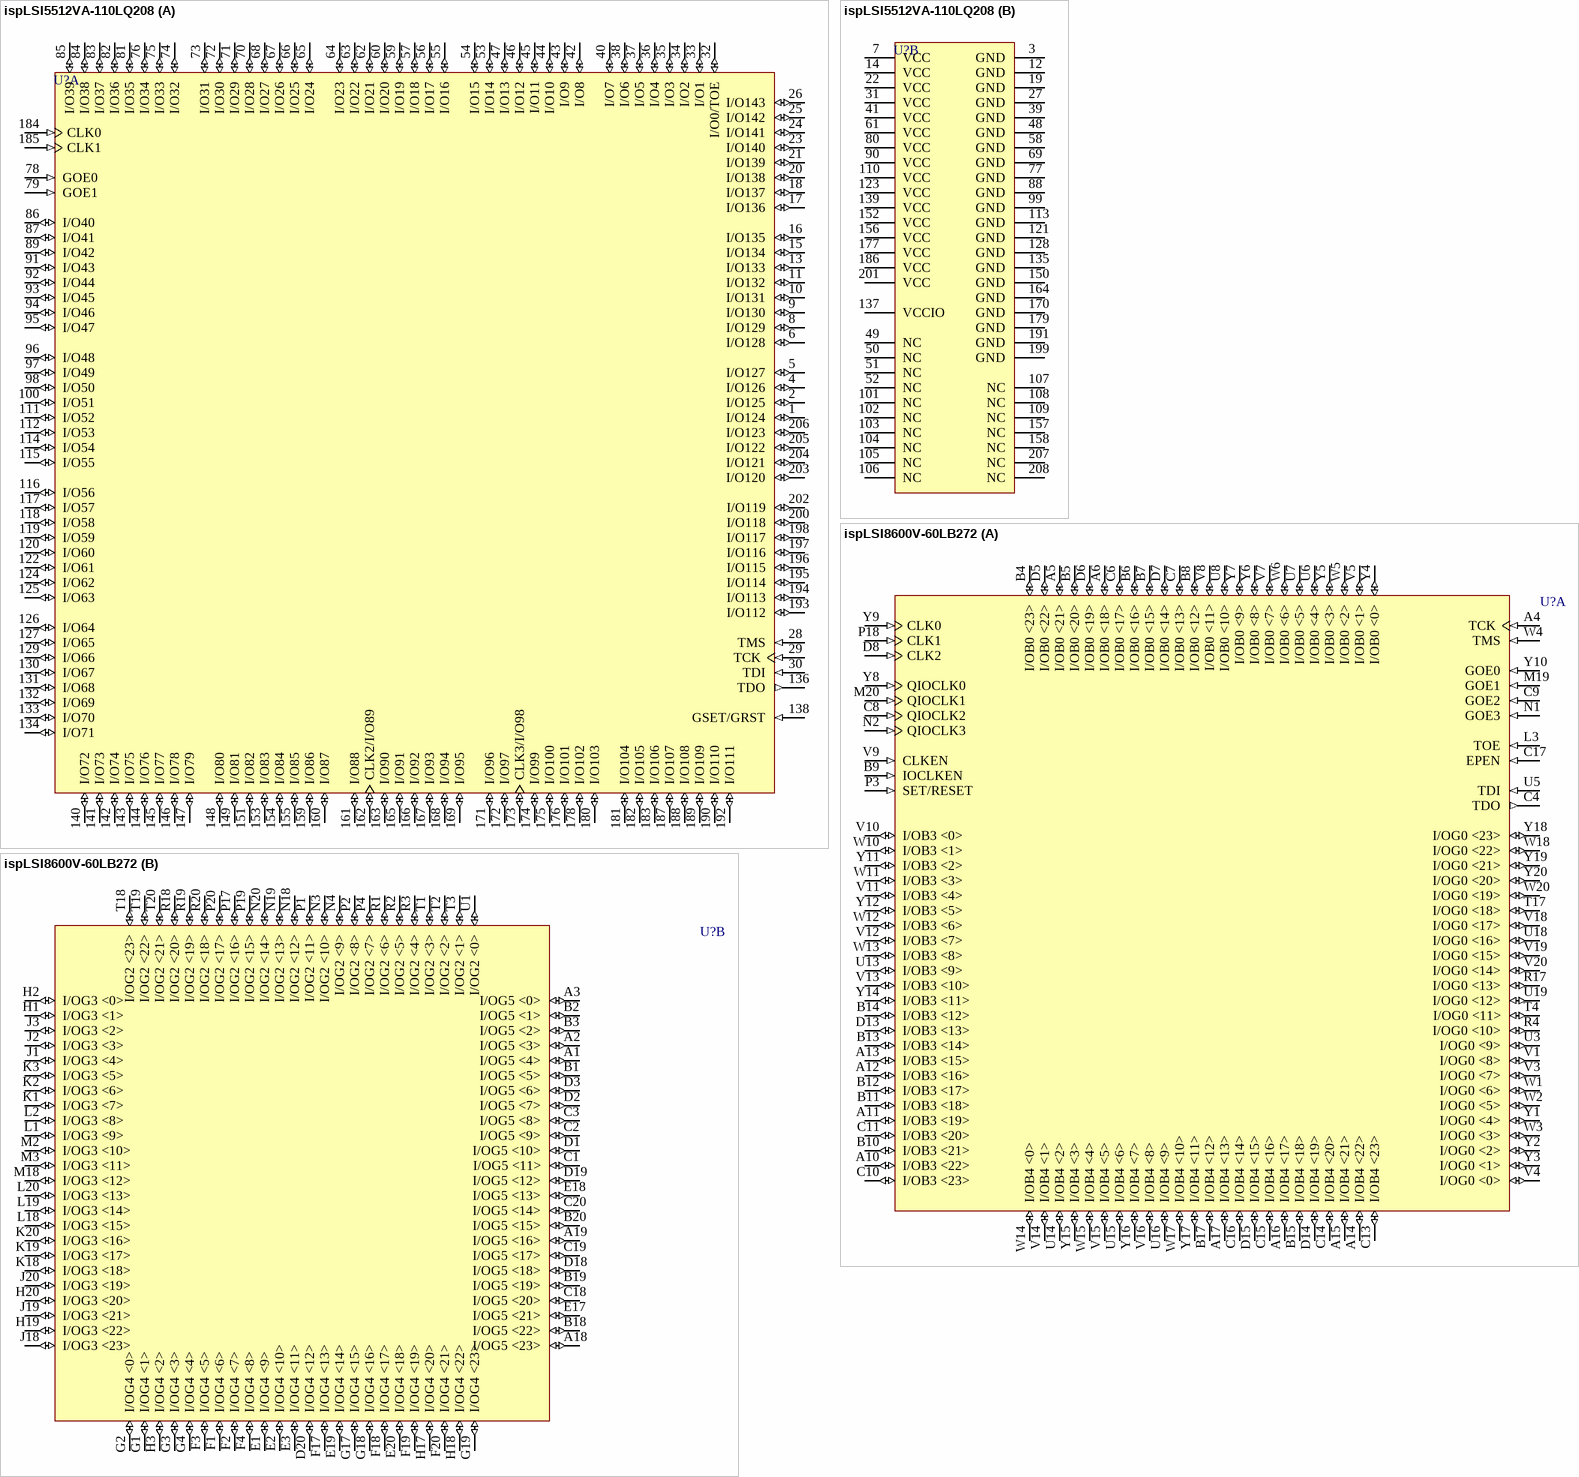
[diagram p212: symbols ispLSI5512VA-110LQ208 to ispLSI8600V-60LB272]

## ispLSI5512VA-110LQ208
designator U?
In-System Programmable 3.3V SuperWIDE High Density PLD
footprint PQFP208_N (Shrink QFP, 208-Leads, Body 28x28mm, Pitch 0.5mm, IPC Medium Density)
footprint PQFP208_L (Shrink QFP, 208-Leads, Body 28x28mm, Pitch 0.5mm, IPC High Density)
footprint PQFP208_M (Shrink QFP, 208-Leads, Body 28x28mm, Pitch 0.5mm, IPC Low Density)
3D model 5512VA-PQFP208 (208-Pin Plastic Quad Flat Pack (PQFP208))
part A pins: 1 I/O124 (io), 2 I/O125 (io), 4 I/O126 (io), 5 I/O127 (io), 6 I/O128 (io), 8 I/O129 (io), 9 I/O130 (io), 10 I/O131 (io), 11 I/O132 (io), 13 I/O133 (io), 15 I/O134 (io), 16 I/O135 (io), 17 I/O136 (io), 18 I/O137 (io), 20 I/O138 (io), 21 I/O139 (io), 23 I/O140 (io), 24 I/O141 (io), 25 I/O142 (io), 26 I/O143 (io), 28 TMS (in), 29 TCK (in), 30 TDI (in), 32 I/O0/TOE (io), 33 I/O1 (io), 34 I/O2 (io), 35 I/O3 (io), 36 I/O4 (io), 37 I/O5 (io), 38 I/O6 (io), 40 I/O7 (io), 42 I/O8 (io), 43 I/O9 (io), 44 I/O10 (io), 45 I/O11 (io), 46 I/O12 (io), 47 I/O13 (io), 53 I/O14 (io), 54 I/O15 (io), 55 I/O16 (io), 56 I/O17 (io), 57 I/O18 (io), 59 I/O19 (io), 60 I/O20 (io), 62 I/O21 (io), 63 I/O22 (io), 64 I/O23 (io), 65 I/O24 (io), 66 I/O25 (io), 67 I/O26 (io), 68 I/O27 (io), 70 I/O28 (io), 71 I/O29 (io), 72 I/O30 (io), 73 I/O31 (io), 74 I/O32 (io), 75 I/O33 (io), 76 I/O34 (io), 78 GOE0 (in), 79 GOE1 (in), 81 I/O35 (io), 82 I/O36 (io), 83 I/O37 (io), 84 I/O38 (io), 85 I/O39 (io), 86 I/O40 (io), 87 I/O41 (io), 89 I/O42 (io), 91 I/O43 (io), 92 I/O44 (io), 93 I/O45 (io), 94 I/O46 (io), 95 I/O47 (io), 96 I/O48 (io), 97 I/O49 (io), 98 I/O50 (io), 100 I/O51 (io), 111 I/O52 (io), 112 I/O53 (io), 114 I/O54 (io), 115 I/O55 (io), 116 I/O56 (io), 117 I/O57 (io), 118 I/O58 (io), 119 I/O59 (io), 120 I/O60 (io), 122 I/O61 (io), 124 I/O62 (io), 125 I/O63 (io), 126 I/O64 (io), 127 I/O65 (io), 129 I/O66 (io), 130 I/O67 (io), 131 I/O68 (io), 132 I/O69 (io), 133 I/O70 (io), 134 I/O71 (io), 136 TDO (out), 138 GSET/GRST (in), 140 I/O72 (io), 141 I/O73 (io), 142 I/O74 (io), 143 I/O75 (io), 144 I/O76 (io), 145 I/O77 (io), 146 I/O78 (io), 147 I/O79 (io), 148 I/O80 (io), 149 I/O81 (io), 151 I/O82 (io), 153 I/O83 (io), 154 I/O84 (io), 155 I/O85 (io), 159 I/O86 (io), 160 I/O87 (io), 161 I/O88 (io), 162 CLK2/I/O89 (io), 163 I/O90 (io), 165 I/O91 (io), 166 I/O92 (io), 167 I/O93 (io), 168 I/O94 (io), 169 I/O95 (io), 171 I/O96 (io), 172 I/O97 (io), 173 CLK3/I/O98 (io), 174 I/O99 (io), 175 I/O100 (io), 176 I/O101 (io), 178 I/O102 (io), 180 I/O103 (io), 181 I/O104 (io), 182 I/O105 (io), 183 I/O106 (io), 184 CLK0 (in), 185 CLK1 (in), 187 I/O107 (io), 188 I/O108 (io), 189 I/O109 (io), 190 I/O110 (io), 192 I/O111 (io), 193 I/O112 (io), 194 I/O113 (io), 195 I/O114 (io), 196 I/O115 (io), 197 I/O116 (io), 198 I/O117 (io), 200 I/O118 (io), 202 I/O119 (io), 203 I/O120 (io), 204 I/O121 (io), 205 I/O122 (io), 206 I/O123 (io)
part B pins: 3 GND (power), 7 VCC (power), 12 GND (power), 14 VCC (power), 19 GND (power), 22 VCC (power), 27 GND (power), 31 VCC (power), 39 GND (power), 41 VCC (power), 48 GND (power), 49 NC, 50 NC, 51 NC, 52 NC, 58 GND (power), 61 VCC (power), 69 GND (power), 77 GND (power), 80 VCC (power), 88 GND (power), 90 VCC (power), 99 GND (power), 101 NC, 102 NC, 103 NC, 104 NC, 105 NC, 106 NC, 107 NC, 108 NC, 109 NC, 110 VCC (power), 113 GND (power), 121 GND (power), 123 VCC (power), 128 GND (power), 135 GND (power), 137 VCCIO (power), 139 VCC (power), 150 GND (power), 152 VCC (power), 156 VCC (power), 157 NC, 158 NC, 164 GND (power), 170 GND (power), 177 VCC (power), 179 GND (power), 186 VCC (power), 191 GND (power), 199 GND (power), 201 VCC (power), 207 NC, 208 NC

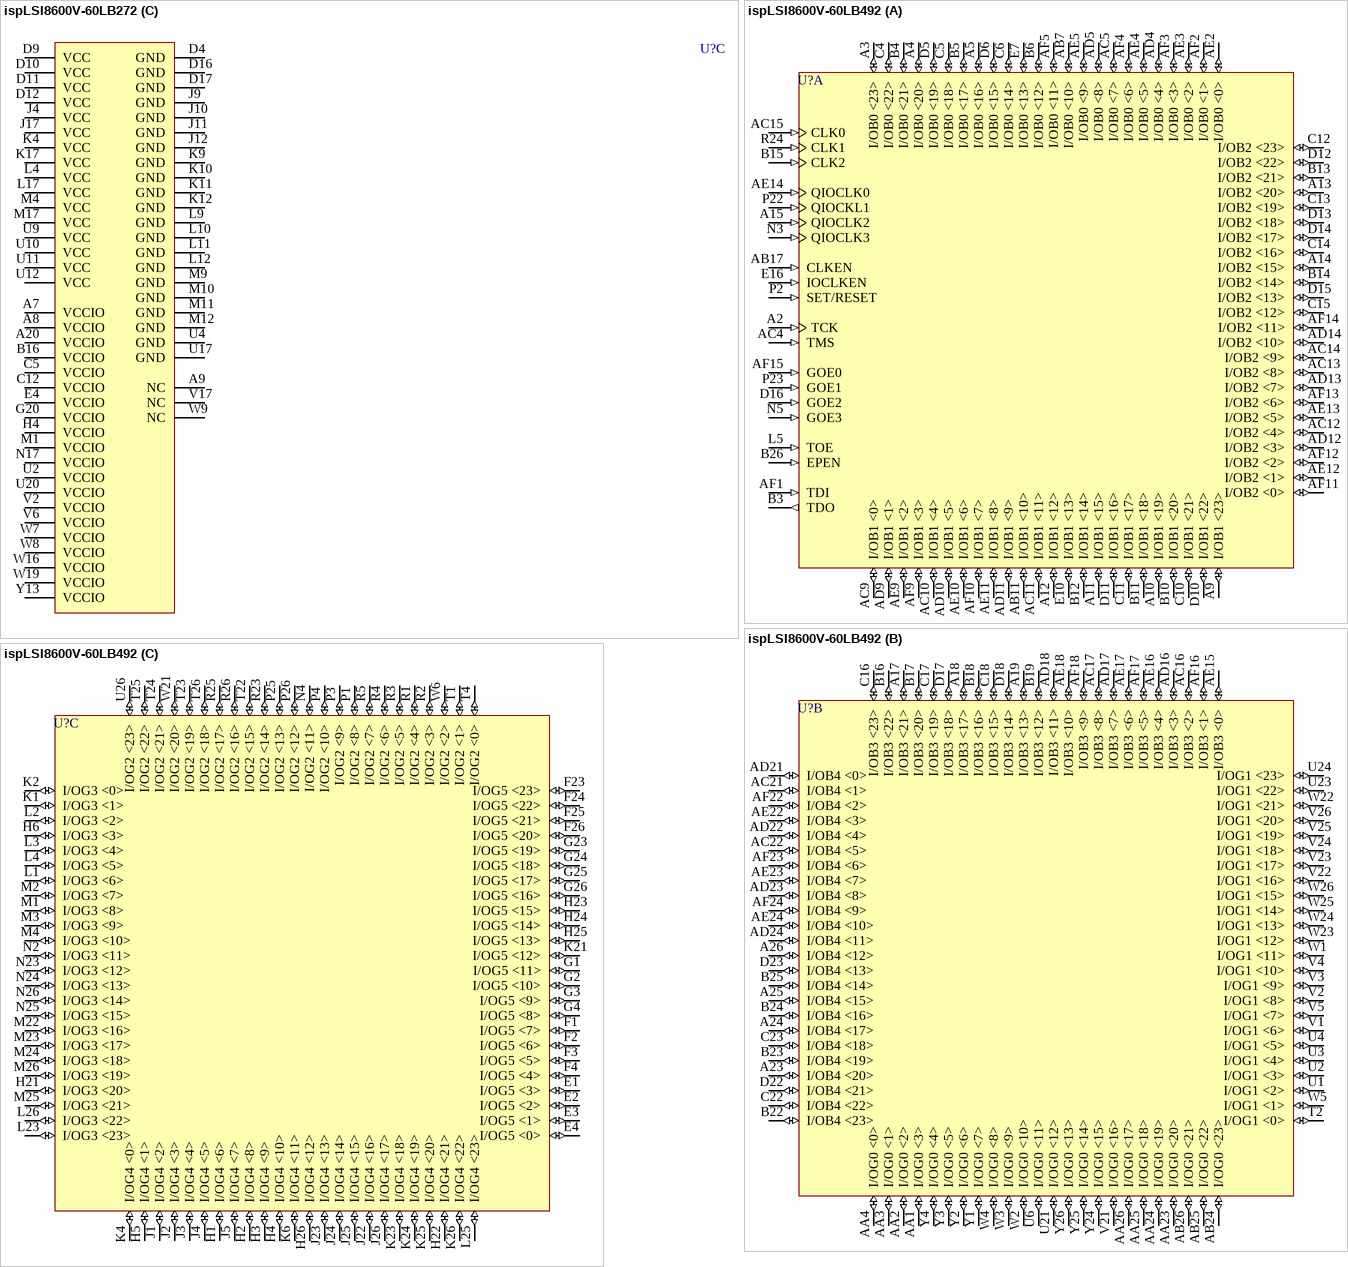
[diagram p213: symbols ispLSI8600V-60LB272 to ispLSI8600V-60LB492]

## ispLSI8600V-60LB272
designator U?
3.3V In-System Programmable SuperBIG High Density PLD
footprint BGA272 (BGA, 272-Leads, Body 27x27mm, Pitch 1.27mm)
3D model 8600V-BGA272 (272-Ball Ball Grid Array (BGA272))
part A pins: A4 TCK (in), A5 I/OB0 <21> (io), A6 I/OB0 <18> (io), A10 I/OB3 <22> (io), A11 I/OB3 <19> (io), A12 I/OB3 <16> (io), A13 I/OB3 <15> (io), A14 I/OB4 <22> (io), A15 I/OB4 <21> (io), A16 I/OB4 <17> (io), A17 I/OB4 <13> (io), B4 I/OB0 <23> (io), B5 I/OB0 <20> (io), B6 I/OB0 <16> (io), B7 I/OB0 <15> (io), B8 I/OB0 <12> (io), B9 IOCLKEN (in), B10 I/OB3 <21> (io), B11 I/OB3 <18> (io), B12 I/OB3 <17> (io), B13 I/OB3 <14> (io), B14 I/OB3 <12> (io), B15 I/OB4 <18> (io), B17 I/OB4 <12> (io), C4 TDO (out), C6 I/OB0 <17> (io), C7 I/OB0 <13> (io), C8 QIOCLK2 (in), C9 GOE2 (in), C10 I/OB3 <23> (io), C11 I/OB3 <20> (io), C13 I/OB4 <23> (io), C14 I/OB4 <20> (io), C15 I/OB4 <16> (io), C16 I/OB4 <14> (io), C17 EPEN (in), D5 I/OB0 <22> (io), D6 I/OB0 <19> (io), D7 I/OB0 <14> (io), D8 CLK2 (in), D13 I/OB3 <13> (io), D14 I/OB4 <19> (io), D15 I/OB4 <15> (io), L3 TOE (in), M19 GOE1 (in), M20 QIOCLK1 (in), N1 GOE3 (in), N2 QIOCLK3 (in), P3 SET/RESET (in), P18 CLK1 (in), R4 I/OG0 <10> (io), R17 I/OG0 <13> (io), T4 I/OG0 <11> (io), T17 I/OG0 <18> (io), U3 I/OG0 <9> (io), U5 TDI (in), U6 I/OB0 <4> (io), U7 I/OB0 <5> (io), U8 I/OB0 <10> (io), U13 I/OB3 <9> (io), U14 I/OB4 <2> (io), U15 I/OB4 <6> (io), U16 I/OB4 <9> (io), U18 I/OG0 <16> (io), U19 I/OG0 <12> (io), V1 I/OG0 <8> (io), V3 I/OG0 <7> (io), V4 I/OG0 <0> (io), V5 I/OB0 <1> (io), V7 I/OB0 <7> (io), V8 I/OB0 <11> (io), V9 CLKEN (in), V10 I/OB3 <0> (io), V11 I/OB3 <4> (io), V12 I/OB3 <7> (io), V13 I/OB3 <10> (io), V14 I/OB4 <1> (io), V15 I/OB4 <5> (io), V16 I/OB4 <8> (io), V18 I/OG0 <17> (io), V19 I/OG0 <15> (io), V20 I/OG0 <14> (io), W1 I/OG0 <6> (io), W2 I/OG0 <5> (io), W3 I/OG0 <3> (io), W4 TMS (in), W5 I/OB0 <2> (io), W6 I/OB0 <6> (io), W10 I/OB3 <1> (io), W11 I/OB3 <3> (io), W12 I/OB3 <6> (io), W13 I/OB3 <8> (io), W14 I/OB4 <0> (io), W15 I/OB4 <4> (io), W17 I/OB4 <10> (io), W18 I/OG0 <22> (io), W20 I/OG0 <19> (io), Y1 I/OG0 <4> (io), Y2 I/OG0 <2> (io), Y3 I/OG0 <1> (io), Y4 I/OB0 <0> (io), Y5 I/OB0 <3> (io), Y6 I/OB0 <8> (io), Y7 I/OB0 <9> (io), Y8 QIOCLK0 (in), Y9 CLK0 (in), Y10 GOE0 (in), Y11 I/OB3 <2> (io), Y12 I/OB3 <5> (io), Y14 I/OB3 <11> (io), Y15 I/OB4 <3> (io), Y16 I/OB4 <7> (io), Y17 I/OB4 <11> (io), Y18 I/OG0 <23> (io), Y19 I/OG0 <21> (io), Y20 I/OG0 <20> (io)
part B pins: A1 I/OG5 <4> (io), A2 I/OG5 <3> (io), A3 I/OG5 <0> (io), A18 I/OG5 <23> (io), A19 I/OG5 <16> (io), B1 I/OG5 <5> (io), B2 I/OG5 <1> (io), B3 I/OG5 <2> (io), B18 I/OG5 <22> (io), B19 I/OG5 <19> (io), B20 I/OG5 <15> (io), C1 I/OG5 <11> (io), C2 I/OG5 <9> (io), C3 I/OG5 <8> (io), C18 I/OG5 <20> (io), C19 I/OG5 <17> (io), C20 I/OG5 <14> (io), D1 I/OG5 <10> (io), D2 I/OG5 <7> (io), D3 I/OG5 <6> (io), D18 I/OG5 <18> (io), D19 I/OG5 <12> (io), D20 I/OG4 <12> (io), E1 I/OG4 <9> (io), E2 I/OG4 <10> (io), E3 I/OG4 <11> (io), E17 I/OG5 <21> (io), E18 I/OG5 <13> (io), E19 I/OG4 <14> (io), E20 I/OG4 <18> (io), F1 I/OG4 <6> (io), F2 I/OG4 <7> (io), F3 I/OG4 <5> (io), F4 I/OG4 <8> (io), F17 I/OG4 <13> (io), F18 I/OG4 <17> (io), F19 I/OG4 <19> (io), F20 I/OG4 <21> (io), G1 I/OG4 <1> (io), G2 I/OG4 <0> (io), G3 I/OG4 <3> (io), G4 I/OG4 <4> (io), G17 I/OG4 <15> (io), G18 I/OG4 <16> (io), G19 I/OG4 <23> (io), H1 I/OG3 <1> (io), H2 I/OG3 <0> (io), H3 I/OG4 <2> (io), H17 I/OG4 <20> (io), H18 I/OG4 <22> (io), H19 I/OG3 <22> (io), H20 I/OG3 <20> (io), J1 I/OG3 <4> (io), J2 I/OG3 <3> (io), J3 I/OG3 <2> (io), J18 I/OG3 <23> (io), J19 I/OG3 <21> (io), J20 I/OG3 <19> (io), K1 I/OG3 <7> (io), K2 I/OG3 <6> (io), K3 I/OG3 <5> (io), K18 I/OG3 <18> (io), K19 I/OG3 <17> (io), K20 I/OG3 <16> (io), L1 I/OG3 <9> (io), L2 I/OG3 <8> (io), L18 I/OG3 <15> (io), L19 I/OG3 <14> (io), L20 I/OG3 <13> (io), M2 I/OG3 <10> (io), M3 I/OG3 <11> (io), M18 I/OG3 <12> (io), N3 I/OG2 <10> (io), N4 I/OG2 <9> (io), N18 I/OG2 <12> (io), N19 I/OG2 <13> (io), N20 I/OG2 <14> (io), P1 I/OG2 <11> (io), P2 I/OG2 <8> (io), P4 I/OG2 <7> (io), P17 I/OG2 <16> (io), P19 I/OG2 <15> (io), P20 I/OG2 <17> (io), R1 I/OG2 <6> (io), R2 I/OG2 <5> (io), R3 I/OG2 <4> (io), R18 I/OG2 <20> (io), R19 I/OG2 <19> (io), R20 I/OG2 <18> (io), T1 I/OG2 <3> (io), T2 I/OG2 <2> (io), T3 I/OG2 <1> (io), T18 I/OG2 <23> (io), T19 I/OG2 <22> (io), T20 I/OG2 <21> (io), U1 I/OG2 <0> (io)
part C pins: A7 VCCIO (power), A8 VCCIO (power), A9 NC, A20 VCCIO (power), B16 VCCIO (power), C5 VCCIO (power), C12 VCCIO (power), D4 GND (power), D9 VCC (power), D10 VCC (power), D11 VCC (power), D12 VCC (power), D16 GND (power), D17 GND (power), E4 VCCIO (power), G20 VCCIO (power), H4 VCCIO (power), J4 VCC (power), J9 GND (power), J10 GND (power), J11 GND (power), J12 GND (power), J17 VCC (power), K4 VCC (power), K9 GND (power), K10 GND (power), K11 GND (power), K12 GND (power), K17 VCC (power), L4 VCC (power), L9 GND (power), L10 GND (power), L11 GND (power), L12 GND (power), L17 VCC (power), M1 VCCIO (power), M4 VCC (power), M9 GND (power), M10 GND (power), M11 GND (power), M12 GND (power), M17 VCC (power), N17 VCCIO (power), U2 VCCIO (power), U4 GND (power), U9 VCC (power), U10 VCC (power), U11 VCC (power), U12 VCC (power), U17 GND (power), U20 VCCIO (power), V2 VCCIO (power), V6 VCCIO (power), V17 NC, W7 VCCIO (power), W8 VCCIO (power), W9 NC, W16 VCCIO (power), W19 VCCIO (power), Y13 VCCIO (power)

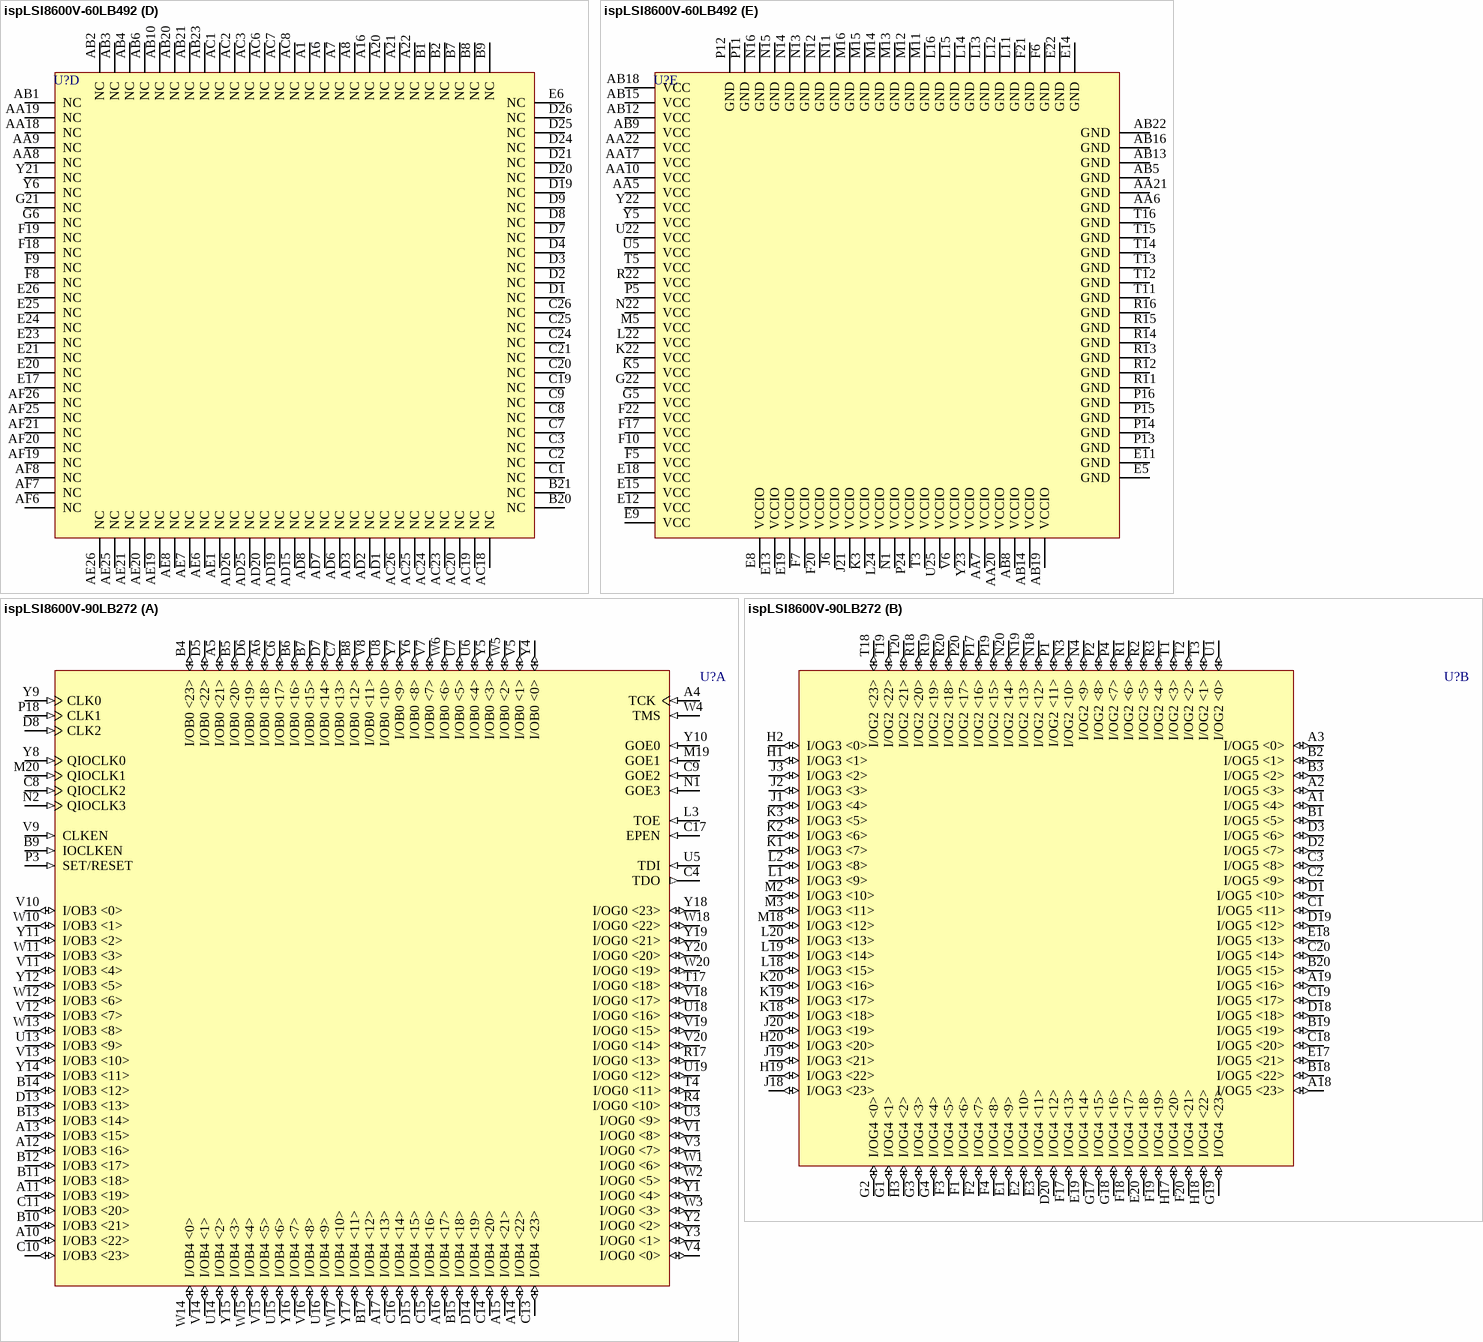
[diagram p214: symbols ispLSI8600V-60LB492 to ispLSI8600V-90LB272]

## ispLSI8600V-60LB492
designator U?
3.3V In-System Programmable SuperBIG High Density PLD
footprint BGA492 (BGA, 492-Leads, Body 35x35mm, Pitch 1.27mm)
3D model 8600V-BGA492 (492-Ball Ball Grid Array (BGA492))
part A pins: A2 TCK (in), A3 I/OB0 <23> (io), A4 I/OB0 <20> (io), A5 I/OB0 <16> (io), A9 I/OB1 <23> (io), A10 I/OB1 <19> (io), A11 I/OB1 <15> (io), A12 I/OB1 <12> (io), A13 I/OB2 <20> (io), A14 I/OB2 <15> (io), A15 QIOCLK2 (in), AB7 I/OB0 <10> (io), AB11 I/OB1 <10> (io), AB17 CLKEN (in), AC4 TMS (in), AC5 I/OB0 <7> (io), AC9 I/OB1 <0> (io), AC10 I/OB1 <4> (io), AC11 I/OB1 <11> (io), AC12 I/OB2 <4> (io), AC13 I/OB2 <8> (io), AC14 I/OB2 <9> (io), AC15 CLK0 (in), AD4 I/OB0 <4> (io), AD5 I/OB0 <8> (io), AD9 I/OB1 <1> (io), AD10 I/OB1 <5> (io), AD11 I/OB1 <9> (io), AD12 I/OB2 <3> (io), AD13 I/OB2 <7> (io), AD14 I/OB2 <10> (io), AE2 I/OB0 <0> (io), AE3 I/OB0 <2> (io), AE4 I/OB0 <5> (io), AE5 I/OB0 <9> (io), AE9 I/OB1 <2> (io), AE10 I/OB1 <6> (io), AE11 I/OB1 <8> (io), AE12 I/OB2 <1> (io), AE13 I/OB2 <5> (io), AE14 QIOCLK0 (in), AF1 TDI (in), AF2 I/OB0 <1> (io), AF3 I/OB0 <3> (io), AF4 I/OB0 <6> (io), AF5 I/OB0 <11> (io), AF9 I/OB1 <3> (io), AF10 I/OB1 <7> (io), AF11 I/OB2 <0> (io), AF12 I/OB2 <2> (io), AF13 I/OB2 <6> (io), AF14 I/OB2 <11> (io), AF15 GOE0 (in), B3 TDO (out), B4 I/OB0 <21> (io), B5 I/OB0 <17> (io), B6 I/OB0 <12> (io), B10 I/OB1 <20> (io), B11 I/OB1 <18> (io), B12 I/OB1 <14> (io), B13 I/OB2 <21> (io), B14 I/OB2 <14> (io), B15 CLK2 (in), B26 EPEN (in), C4 I/OB0 <22> (io), C5 I/OB0 <18> (io), C6 I/OB0 <14> (io), C10 I/OB1 <21> (io), C11 I/OB1 <17> (io), C12 I/OB2 <23> (io), C13 I/OB2 <19> (io), C14 I/OB2 <16> (io), C15 I/OB2 <12> (io), D5 I/OB0 <19> (io), D6 I/OB0 <15> (io), D10 I/OB1 <22> (io), D11 I/OB1 <16> (io), D12 I/OB2 <22> (io), D13 I/OB2 <18> (io), D14 I/OB2 <17> (io), D15 I/OB2 <13> (io), D16 GOE2 (in), E7 I/OB0 <13> (io), E10 I/OB1 <13> (io), E16 IOCLKEN (in), L5 TOE (in), N3 QIOCLK3 (in), N5 GOE3 (in), P2 SET/RESET (in), P22 QIOCKL1 (in), P23 GOE1 (in), R24 CLK1 (in)
part B pins: A17 I/OB3 <21> (io), A18 I/OB3 <17> (io), A19 I/OB3 <13> (io), A23 I/OB4 <20> (io), A24 I/OB4 <17> (io), A25 I/OB4 <15> (io), A26 I/OB4 <12> (io), AA1 I/OG0 <3> (io), AA2 I/OG0 <2> (io), AA3 I/OG0 <1> (io), AA4 I/OG0 <0> (io), AA23 I/OG0 <20> (io), AA24 I/OG0 <19> (io), AA25 I/OG0 <18> (io), AA26 I/OG0 <17> (io), AB24 I/OG0 <23> (io), AB25 I/OG0 <22> (io), AB26 I/OG0 <21> (io), AC16 I/OB3 <2> (io), AC17 I/OB3 <8> (io), AC21 I/OB4 <1> (io), AC22 I/OB4 <5> (io), AD16 I/OB3 <3> (io), AD17 I/OB3 <7> (io), AD18 I/OB3 <11> (io), AD21 I/OB4 <0> (io), AD22 I/OB4 <4> (io), AD23 I/OB4 <8> (io), AD24 I/OB4 <11> (io), AE15 I/OB3 <0> (io), AE16 I/OB3 <4> (io), AE17 I/OB3 <6> (io), AE18 I/OB3 <10> (io), AE22 I/OB4 <3> (io), AE23 I/OB4 <7> (io), AE24 I/OB4 <10> (io), AF16 I/OB3 <1> (io), AF17 I/OB3 <5> (io), AF18 I/OB3 <9> (io), AF22 I/OB4 <2> (io), AF23 I/OB4 <6> (io), AF24 I/OB4 <9> (io), B16 I/OB3 <22> (io), B17 I/OB3 <20> (io), B18 I/OB3 <16> (io), B19 I/OB3 <12> (io), B22 I/OB4 <23> (io), B23 I/OB4 <19> (io), B24 I/OB4 <16> (io), B25 I/OB4 <14> (io), C16 I/OB3 <23> (io), C17 I/OB3 <19> (io), C18 I/OB3 <15> (io), C22 I/OB4 <22> (io), C23 I/OB4 <18> (io), D17 I/OB3 <18> (io), D18 I/OB3 <14> (io), D22 I/OB4 <21> (io), D23 I/OB4 <13> (io), T2 I/OG1 <0> (io), U1 I/OG1 <2> (io), U2 I/OG1 <3> (io), U3 I/OG1 <4> (io), U4 I/OG1 <5> (io), U6 I/OG0 <11> (io), U21 I/OG0 <12> (io), U23 I/OG1 <22> (io), U24 I/OG1 <23> (io), V1 I/OG1 <6> (io), V2 I/OG1 <8> (io), V3 I/OG1 <9> (io), V4 I/OG1 <10> (io), V5 I/OG1 <7> (io), V21 I/OG0 <16> (io), V22 I/OG1 <16> (io), V23 I/OG1 <17> (io), V24 I/OG1 <18> (io), V25 I/OG1 <19> (io), V26 I/OG1 <20> (io), W1 I/OG1 <11> (io), W2 I/OG0 <10> (io), W3 I/OG0 <9> (io), W4 I/OG0 <8> (io), W5 I/OG1 <1> (io), W22 I/OG1 <21> (io), W23 I/OG1 <12> (io), W24 I/OG1 <13> (io), W25 I/OG1 <14> (io), W26 I/OG1 <15> (io), Y1 I/OG0 <7> (io), Y2 I/OG0 <6> (io), Y3 I/OG0 <5> (io), Y4 I/OG0 <4> (io), Y24 I/OG0 <15> (io), Y25 I/OG0 <14> (io), Y26 I/OG0 <13> (io)
part C pins: E1 I/OG5 <3> (io), E2 I/OG5 <2> (io), E3 I/OG5 <1> (io), E4 I/OG5 <0> (io), F1 I/OG5 <7> (io), F2 I/OG5 <6> (io), F3 I/OG5 <5> (io), F4 I/OG5 <4> (io), F23 I/OG5 <23> (io), F24 I/OG5 <22> (io), F25 I/OG5 <21> (io), F26 I/OG5 <20> (io), G1 I/OG5 <11> (io), G2 I/OG5 <10> (io), G3 I/OG5 <9> (io), G4 I/OG5 <8> (io), G23 I/OG5 <19> (io), G24 I/OG5 <18> (io), G25 I/OG5 <17> (io), G26 I/OG5 <16> (io), H1 I/OG4 <6> (io), H2 I/OG4 <8> (io), H3 I/OG4 <9> (io), H4 I/OG4 <10> (io), H5 I/OG4 <1> (io), H6 I/OG3 <3> (io), H21 I/OG3 <20> (io), H22 I/OG4 <21> (io), H23 I/OG5 <15> (io), H24 I/OG5 <14> (io), H25 I/OG5 <13> (io), H26 I/OG4 <12> (io), J1 I/OG4 <2> (io), J2 I/OG4 <3> (io), J3 I/OG4 <4> (io), J4 I/OG4 <5> (io), J5 I/OG4 <7> (io), J22 I/OG4 <16> (io), J23 I/OG4 <13> (io), J24 I/OG4 <14> (io), J25 I/OG4 <15> (io), J26 I/OG4 <17> (io), K1 I/OG3 <1> (io), K2 I/OG3 <0> (io), K4 I/OG4 <0> (io), K6 I/OG4 <11> (io), K21 I/OG5 <12> (io), K23 I/OG4 <18> (io), K24 I/OG4 <19> (io), K25 I/OG4 <20> (io), K26 I/OG4 <22> (io), L1 I/OG3 <6> (io), L2 I/OG3 <2> (io), L3 I/OG3 <4> (io), L4 I/OG3 <5> (io), L23 I/OG3 <23> (io), L25 I/OG4 <23> (io), L26 I/OG3 <22> (io), M1 I/OG3 <8> (io), M2 I/OG3 <7> (io), M3 I/OG3 <9> (io), M4 I/OG3 <10> (io), M22 I/OG3 <16> (io), M23 I/OG3 <17> (io), M24 I/OG3 <18> (io), M25 I/OG3 <21> (io), M26 I/OG3 <19> (io), N2 I/OG3 <11> (io), N4 I/OG2 <11> (io), N23 I/OG3 <12> (io), N24 I/OG3 <13> (io), N25 I/OG3 <15> (io), N26 I/OG3 <14> (io), P1 I/OG2 <8> (io), P3 I/OG2 <9> (io), P4 I/OG2 <10> (io), P25 I/OG2 <13> (io), P26 I/OG2 <12> (io), R1 I/OG2 <4> (io), R2 I/OG2 <3> (io), R3 I/OG2 <5> (io), R4 I/OG2 <6> (io), R5 I/OG2 <7> (io), R23 I/OG2 <14> (io), R25 I/OG2 <17> (io), R26 I/OG2 <16> (io), T1 I/OG2 <1> (io), T4 I/OG2 <0> (io), T22 I/OG2 <15> (io), T23 I/OG2 <19> (io), T24 I/OG2 <21> (io), T25 I/OG2 <22> (io), T26 I/OG2 <18> (io), U26 I/OG2 <23> (io), W6 I/OG2 <2> (io), W21 I/OG2 <20> (io)
part D pins: A1 NC, A6 NC, A7 NC, A8 NC, A16 NC, A20 NC, A21 NC, A22 NC, AA8 NC, AA9 NC, AA18 NC, AA19 NC, AB1 NC, AB2 NC, AB3 NC, AB4 NC, AB6 NC, AB10 NC, AB20 NC, AB21 NC, AB23 NC, AC1 NC, AC2 NC, AC3 NC, AC6 NC, AC7 NC, AC8 NC, AC18 NC, AC19 NC, AC20 NC, AC23 NC, AC24 NC, AC25 NC, AC26 NC, AD1 NC, AD2 NC, AD3 NC, AD6 NC, AD7 NC, AD8 NC, AD15 NC, AD19 NC, AD20 NC, AD25 NC, AD26 NC, AE1 NC, AE6 NC, AE7 NC, AE8 NC, AE19 NC, AE20 NC, AE21 NC, AE25 NC, AE26 NC, AF6 NC, AF7 NC, AF8 NC, AF19 NC, AF20 NC, AF21 NC, AF25 NC, AF26 NC, B1 NC, B2 NC, B7 NC, B8 NC, B9 NC, B20 NC, B21 NC, C1 NC, C2 NC, C3 NC, C7 NC, C8 NC, C9 NC, C19 NC, C20 NC, C21 NC, C24 NC, C25 NC, C26 NC, D1 NC, D2 NC, D3 NC, D4 NC, D7 NC, D8 NC, D9 NC, D19 NC, D20 NC, D21 NC, D24 NC, D25 NC, D26 NC, E6 NC, E17 NC, E20 NC, E21 NC, E23 NC, E24 NC, E25 NC, E26 NC, F8 NC, F9 NC, F18 NC, F19 NC, G6 NC, G21 NC, Y6 NC, Y21 NC
part E pins: AA5 VCC (power), AA6 GND (power), AA7 VCCIO (power), AA10 VCC (power), AA17 VCC (power), AA20 VCCIO (power), AA21 GND (power), AA22 VCC (power), AB5 GND (power), AB8 VCCIO (power), AB9 VCC (power), AB12 VCC (power), AB13 GND (power), AB14 VCCIO (power), AB15 VCC (power), AB16 GND (power), AB18 VCC (power), AB19 VCCIO (power), AB22 GND (power), E5 GND (power), E8 VCCIO (power), E9 VCC (power), E11 GND (power), E12 VCC (power), E13 VCCIO (power), E14 GND (power), E15 VCC (power), E18 VCC (power), E19 VCCIO (power), E22 GND (power), F5 VCC (power), F6 GND (power), F7 VCCIO (power), F10 VCC (power), F17 VCC (power), F20 VCCIO (power), F21 GND (power), F22 VCC (power), G5 VCC (power), G22 VCC (power), J6 VCCIO (power), J21 VCCIO (power), K3 VCCIO (power), K5 VCC (power), K22 VCC (power), L11 GND (power), L12 GND (power), L13 GND (power), L14 GND (power), L15 GND (power), L16 GND (power), L22 VCC (power), L24 VCCIO (power), M5 VCC (power), M11 GND (power), M12 GND (power), M13 GND (power), M14 GND (power), M15 GND (power), M16 GND (power), N1 VCCIO (power), N11 GND (power), N12 GND (power), N13 GND (power), N14 GND (power), N15 GND (power), N16 GND (power), N22 VCC (power), P5 VCC (power), P11 GND (power), P12 GND (power), P13 GND (power), P14 GND (power), P15 GND (power), P16 GND (power), P24 VCCIO (power), R11 GND (power), R12 GND (power), R13 GND (power), R14 GND (power), R15 GND (power), R16 GND (power), R22 VCC (power), T3 VCCIO (power), T5 VCC (power), T11 GND (power), T12 GND (power), T13 GND (power), T14 GND (power), T15 GND (power), T16 GND (power), U5 VCC (power), U22 VCC (power), U25 VCCIO (power), V6 VCCIO (power), Y5 VCC (power), Y22 VCC (power), Y23 VCCIO (power)

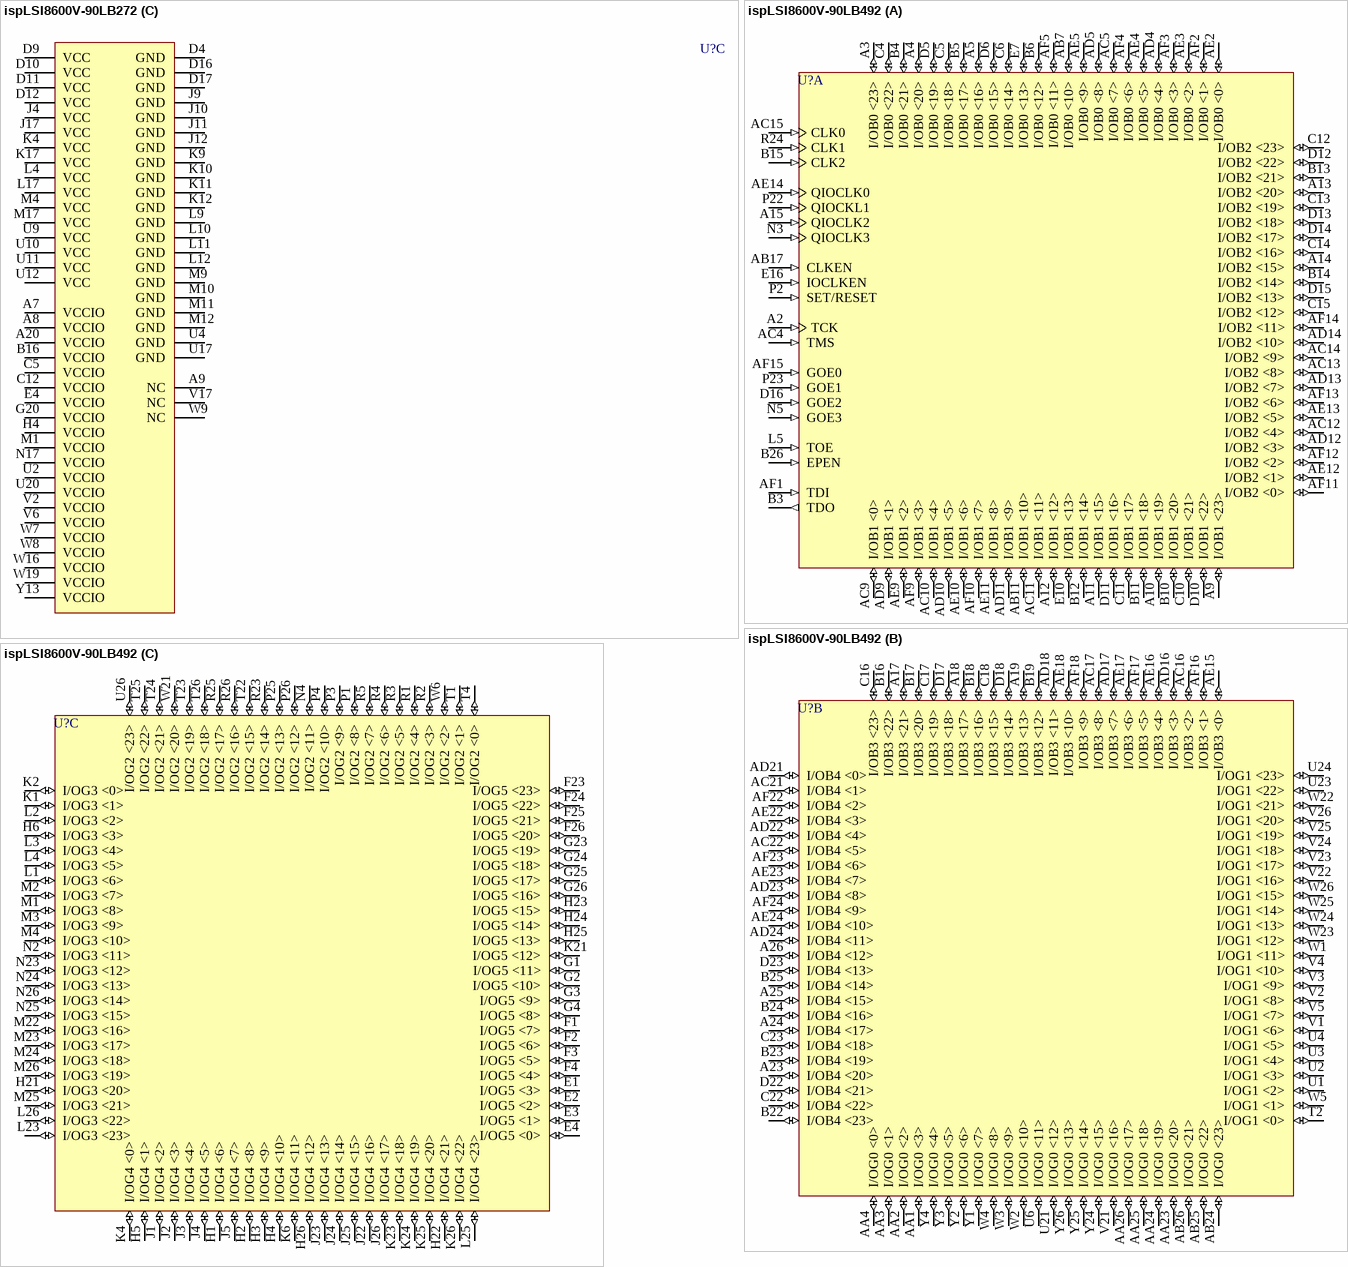
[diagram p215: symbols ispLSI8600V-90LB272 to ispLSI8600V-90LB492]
